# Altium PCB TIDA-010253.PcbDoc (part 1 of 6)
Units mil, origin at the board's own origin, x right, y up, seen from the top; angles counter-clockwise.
Board outline 5525 x 6695 mil, 4 copper layers (Top Layer, Signal Layer 1, Signal Layer 2, Bottom Layer), stack 61.2 mil thick; 522 components, 391 nets, 1722 pads, 1048 vias.
Unrouted connection lines stored in the file: 22.
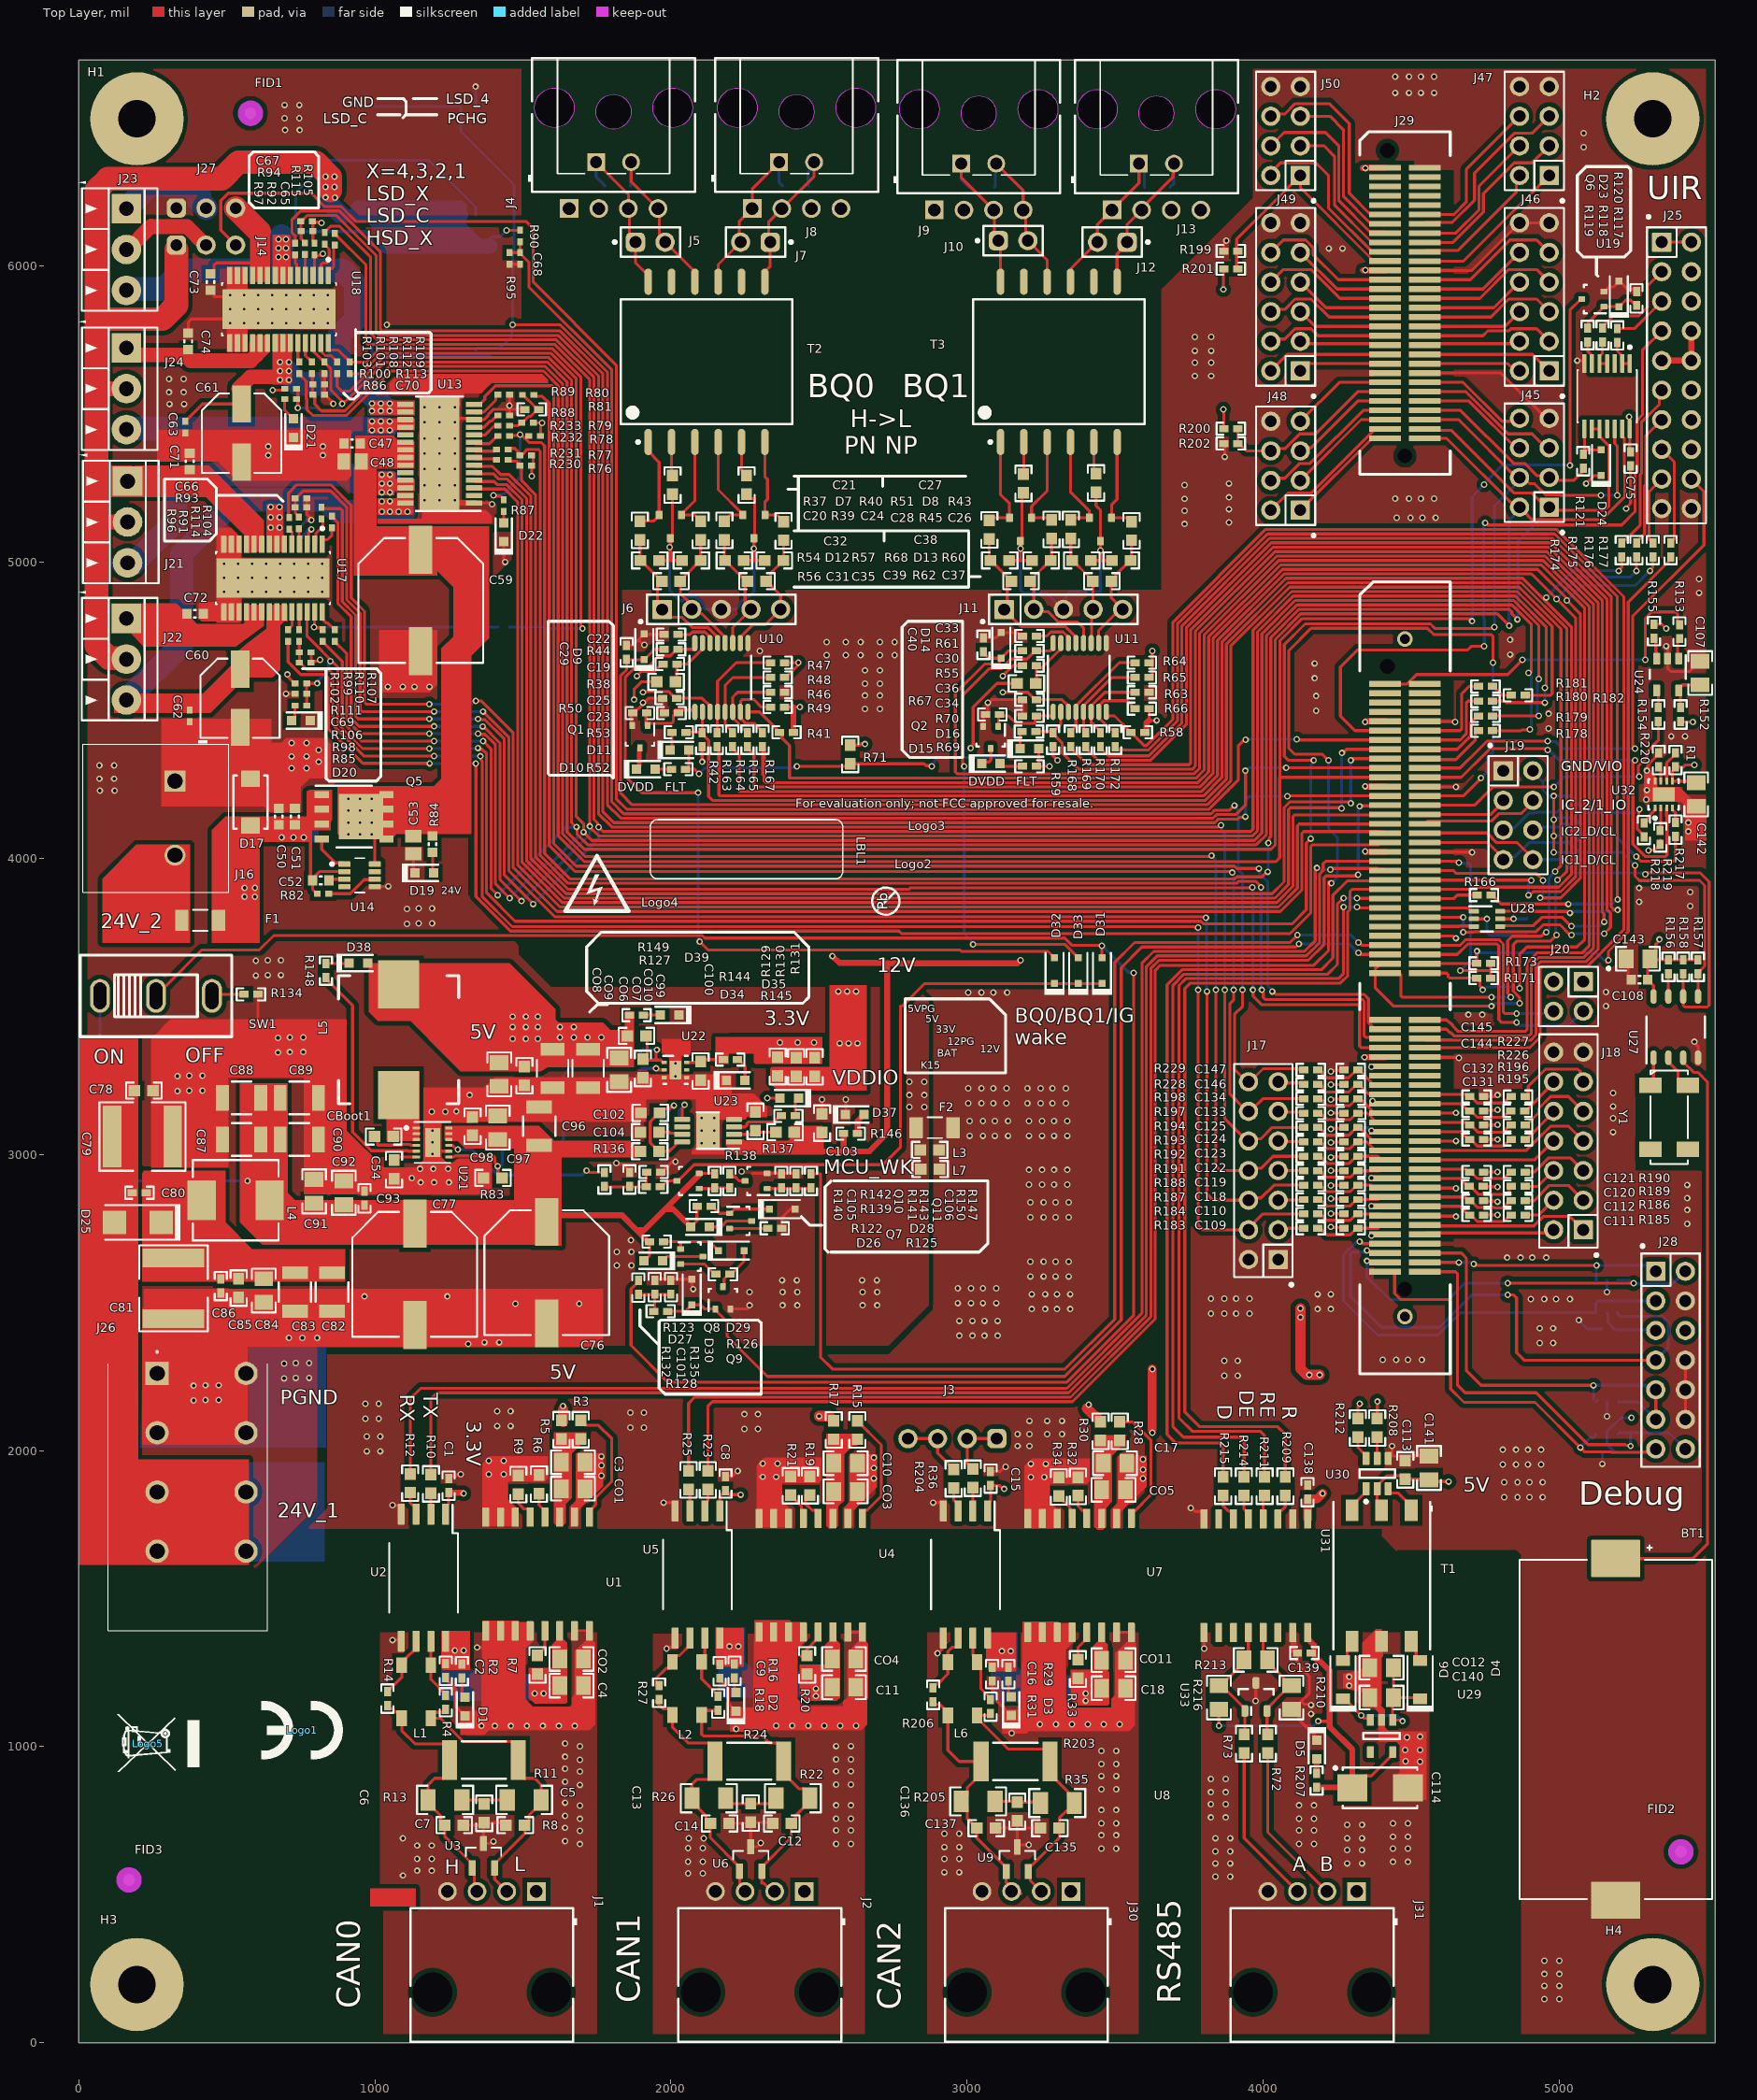
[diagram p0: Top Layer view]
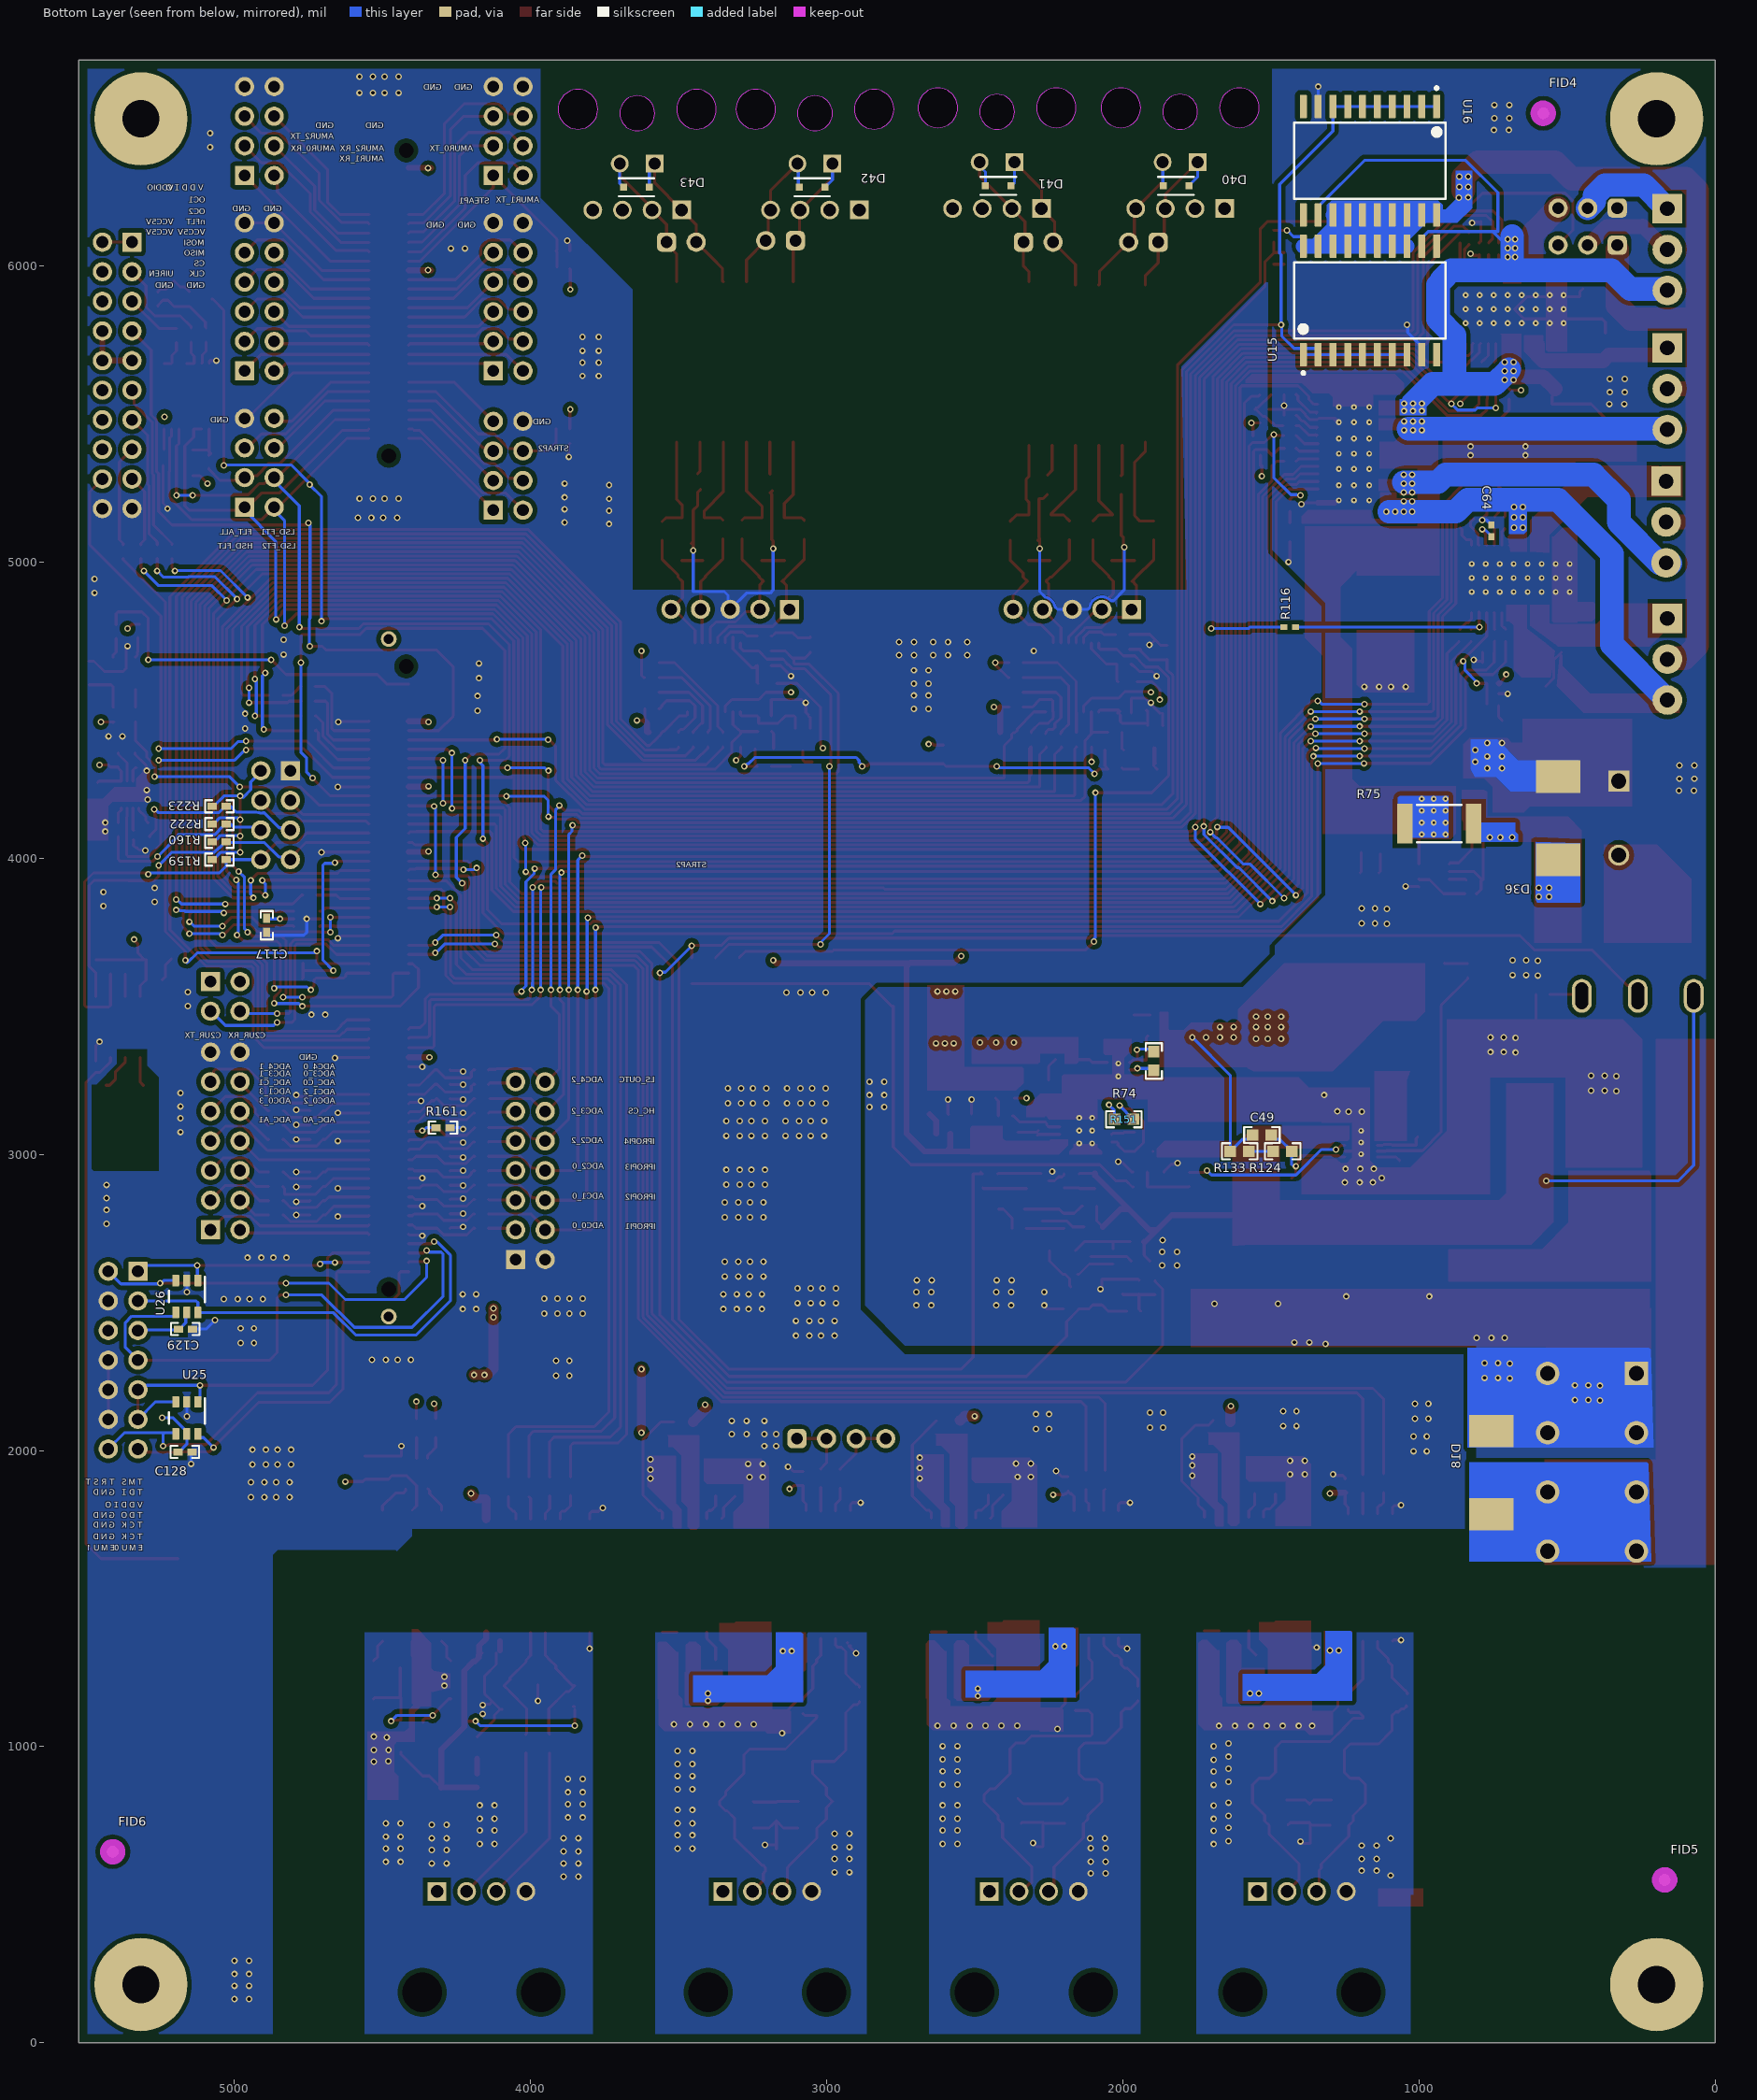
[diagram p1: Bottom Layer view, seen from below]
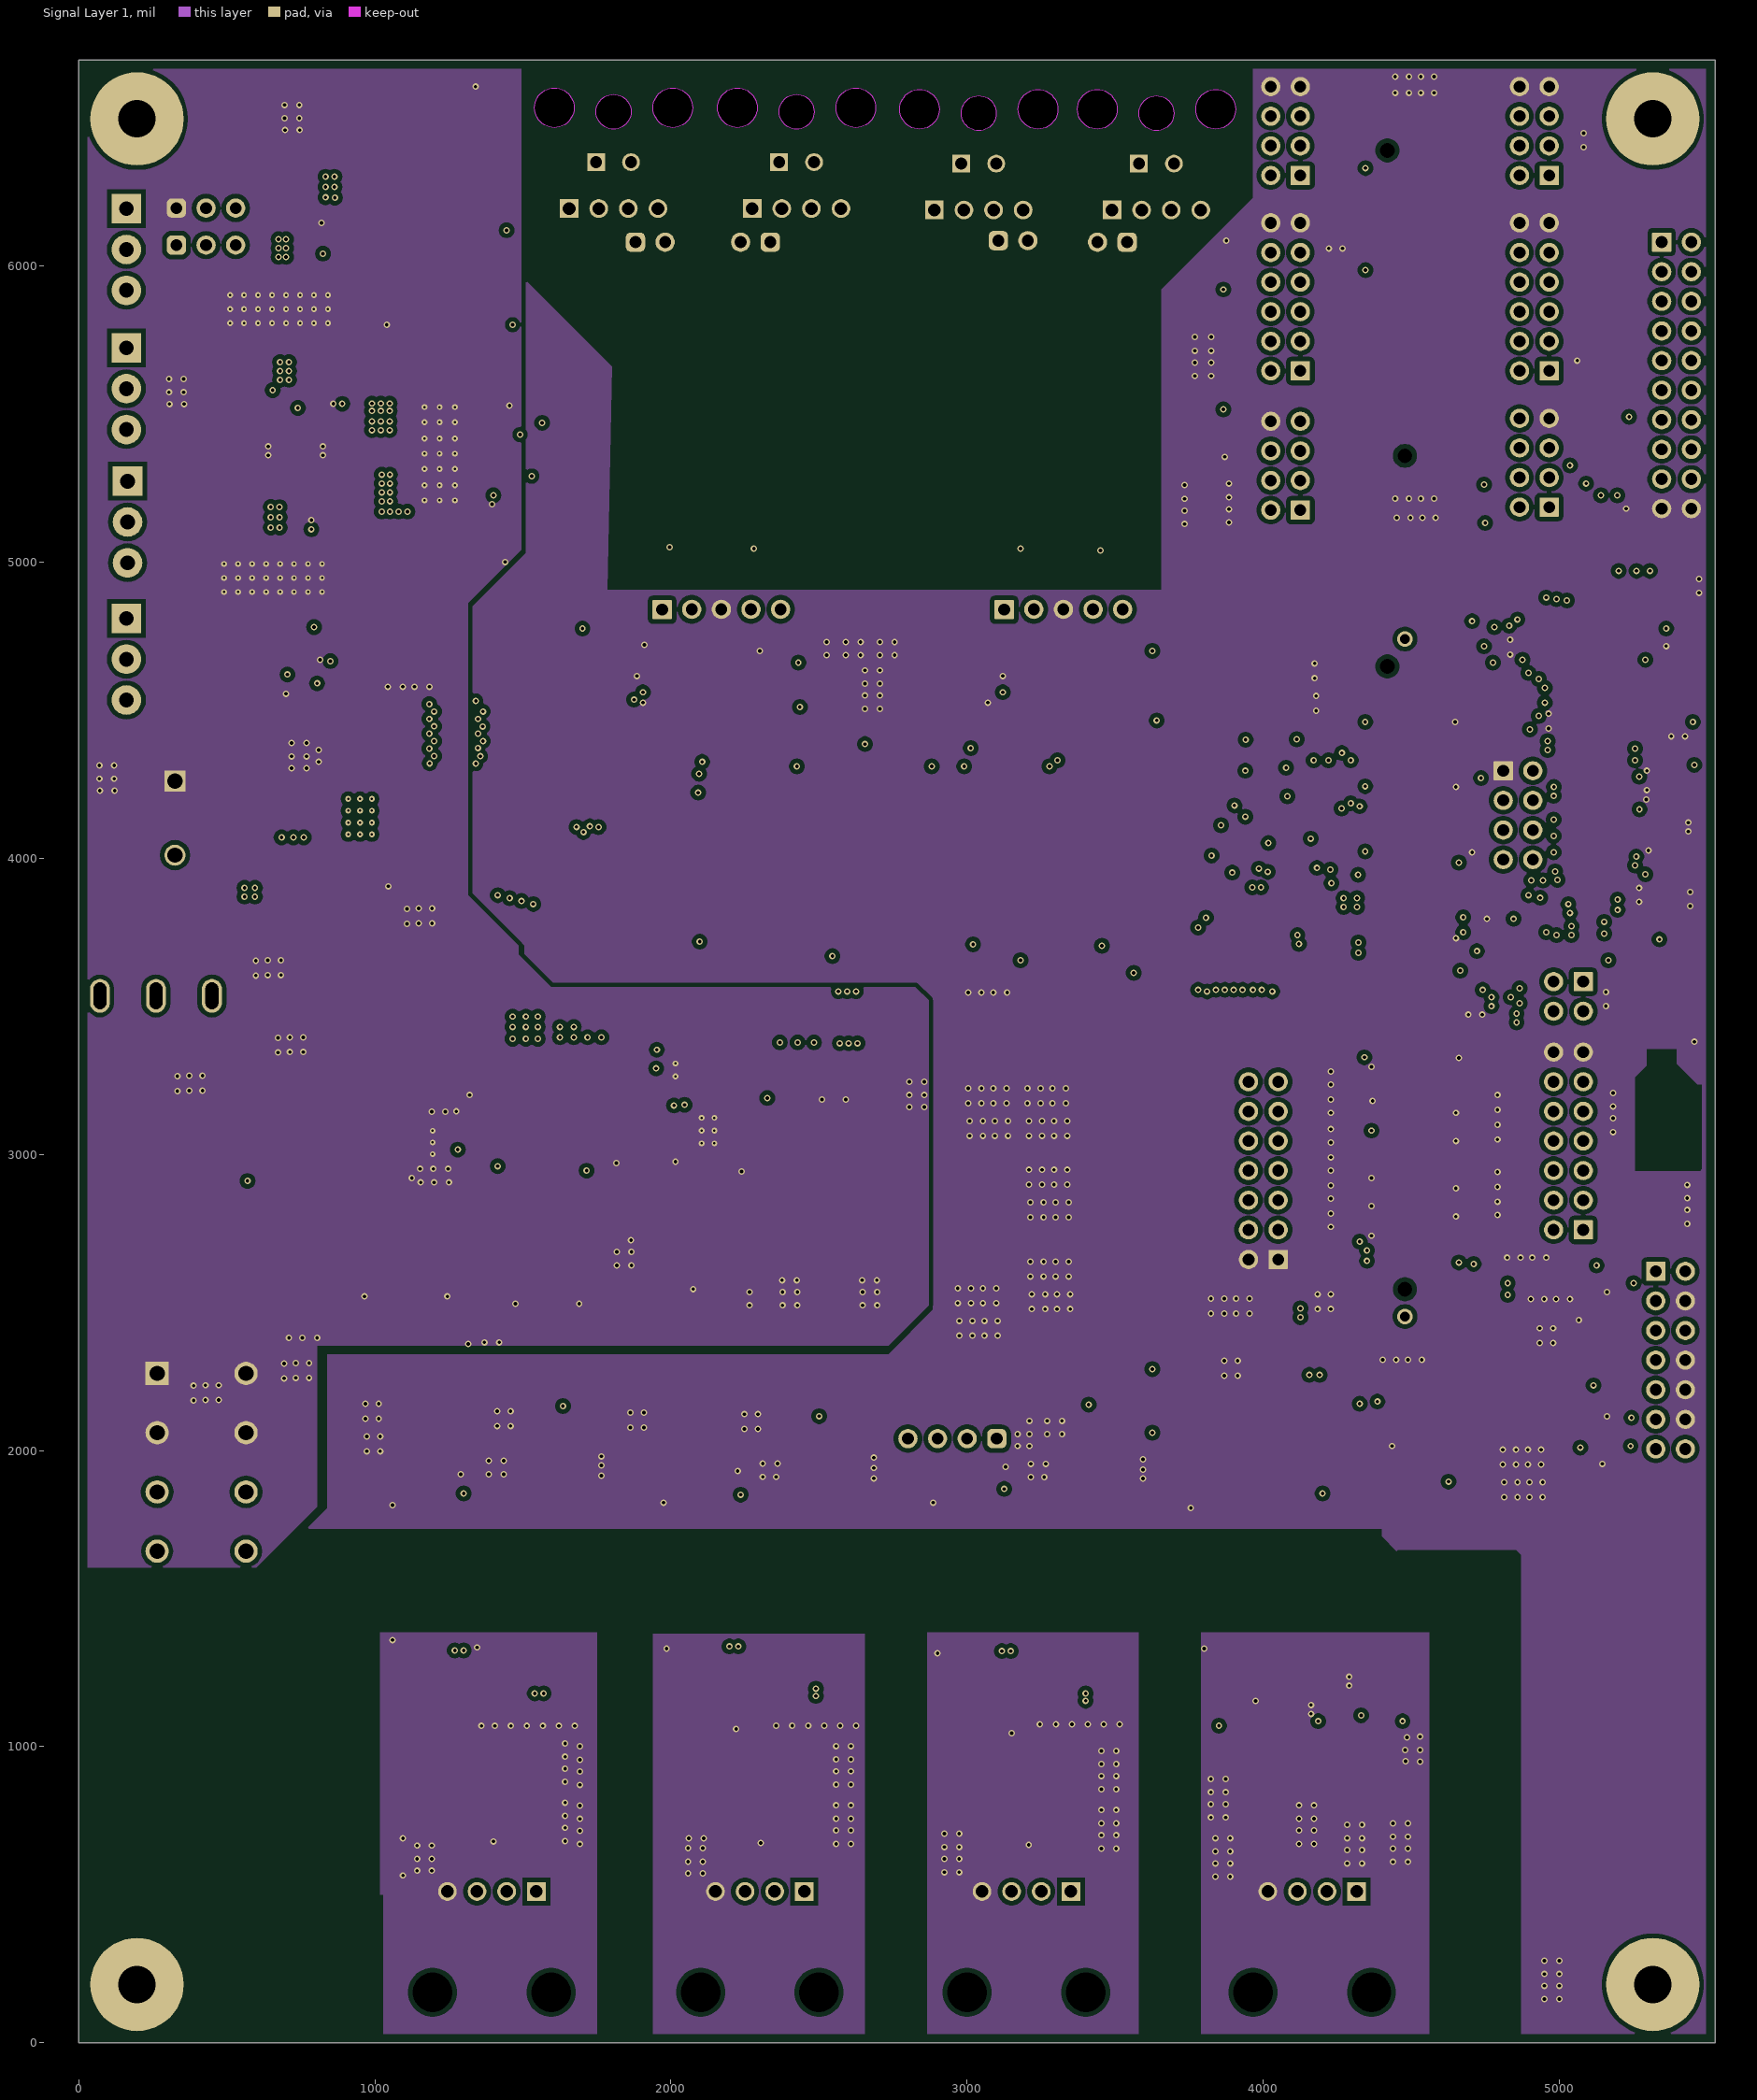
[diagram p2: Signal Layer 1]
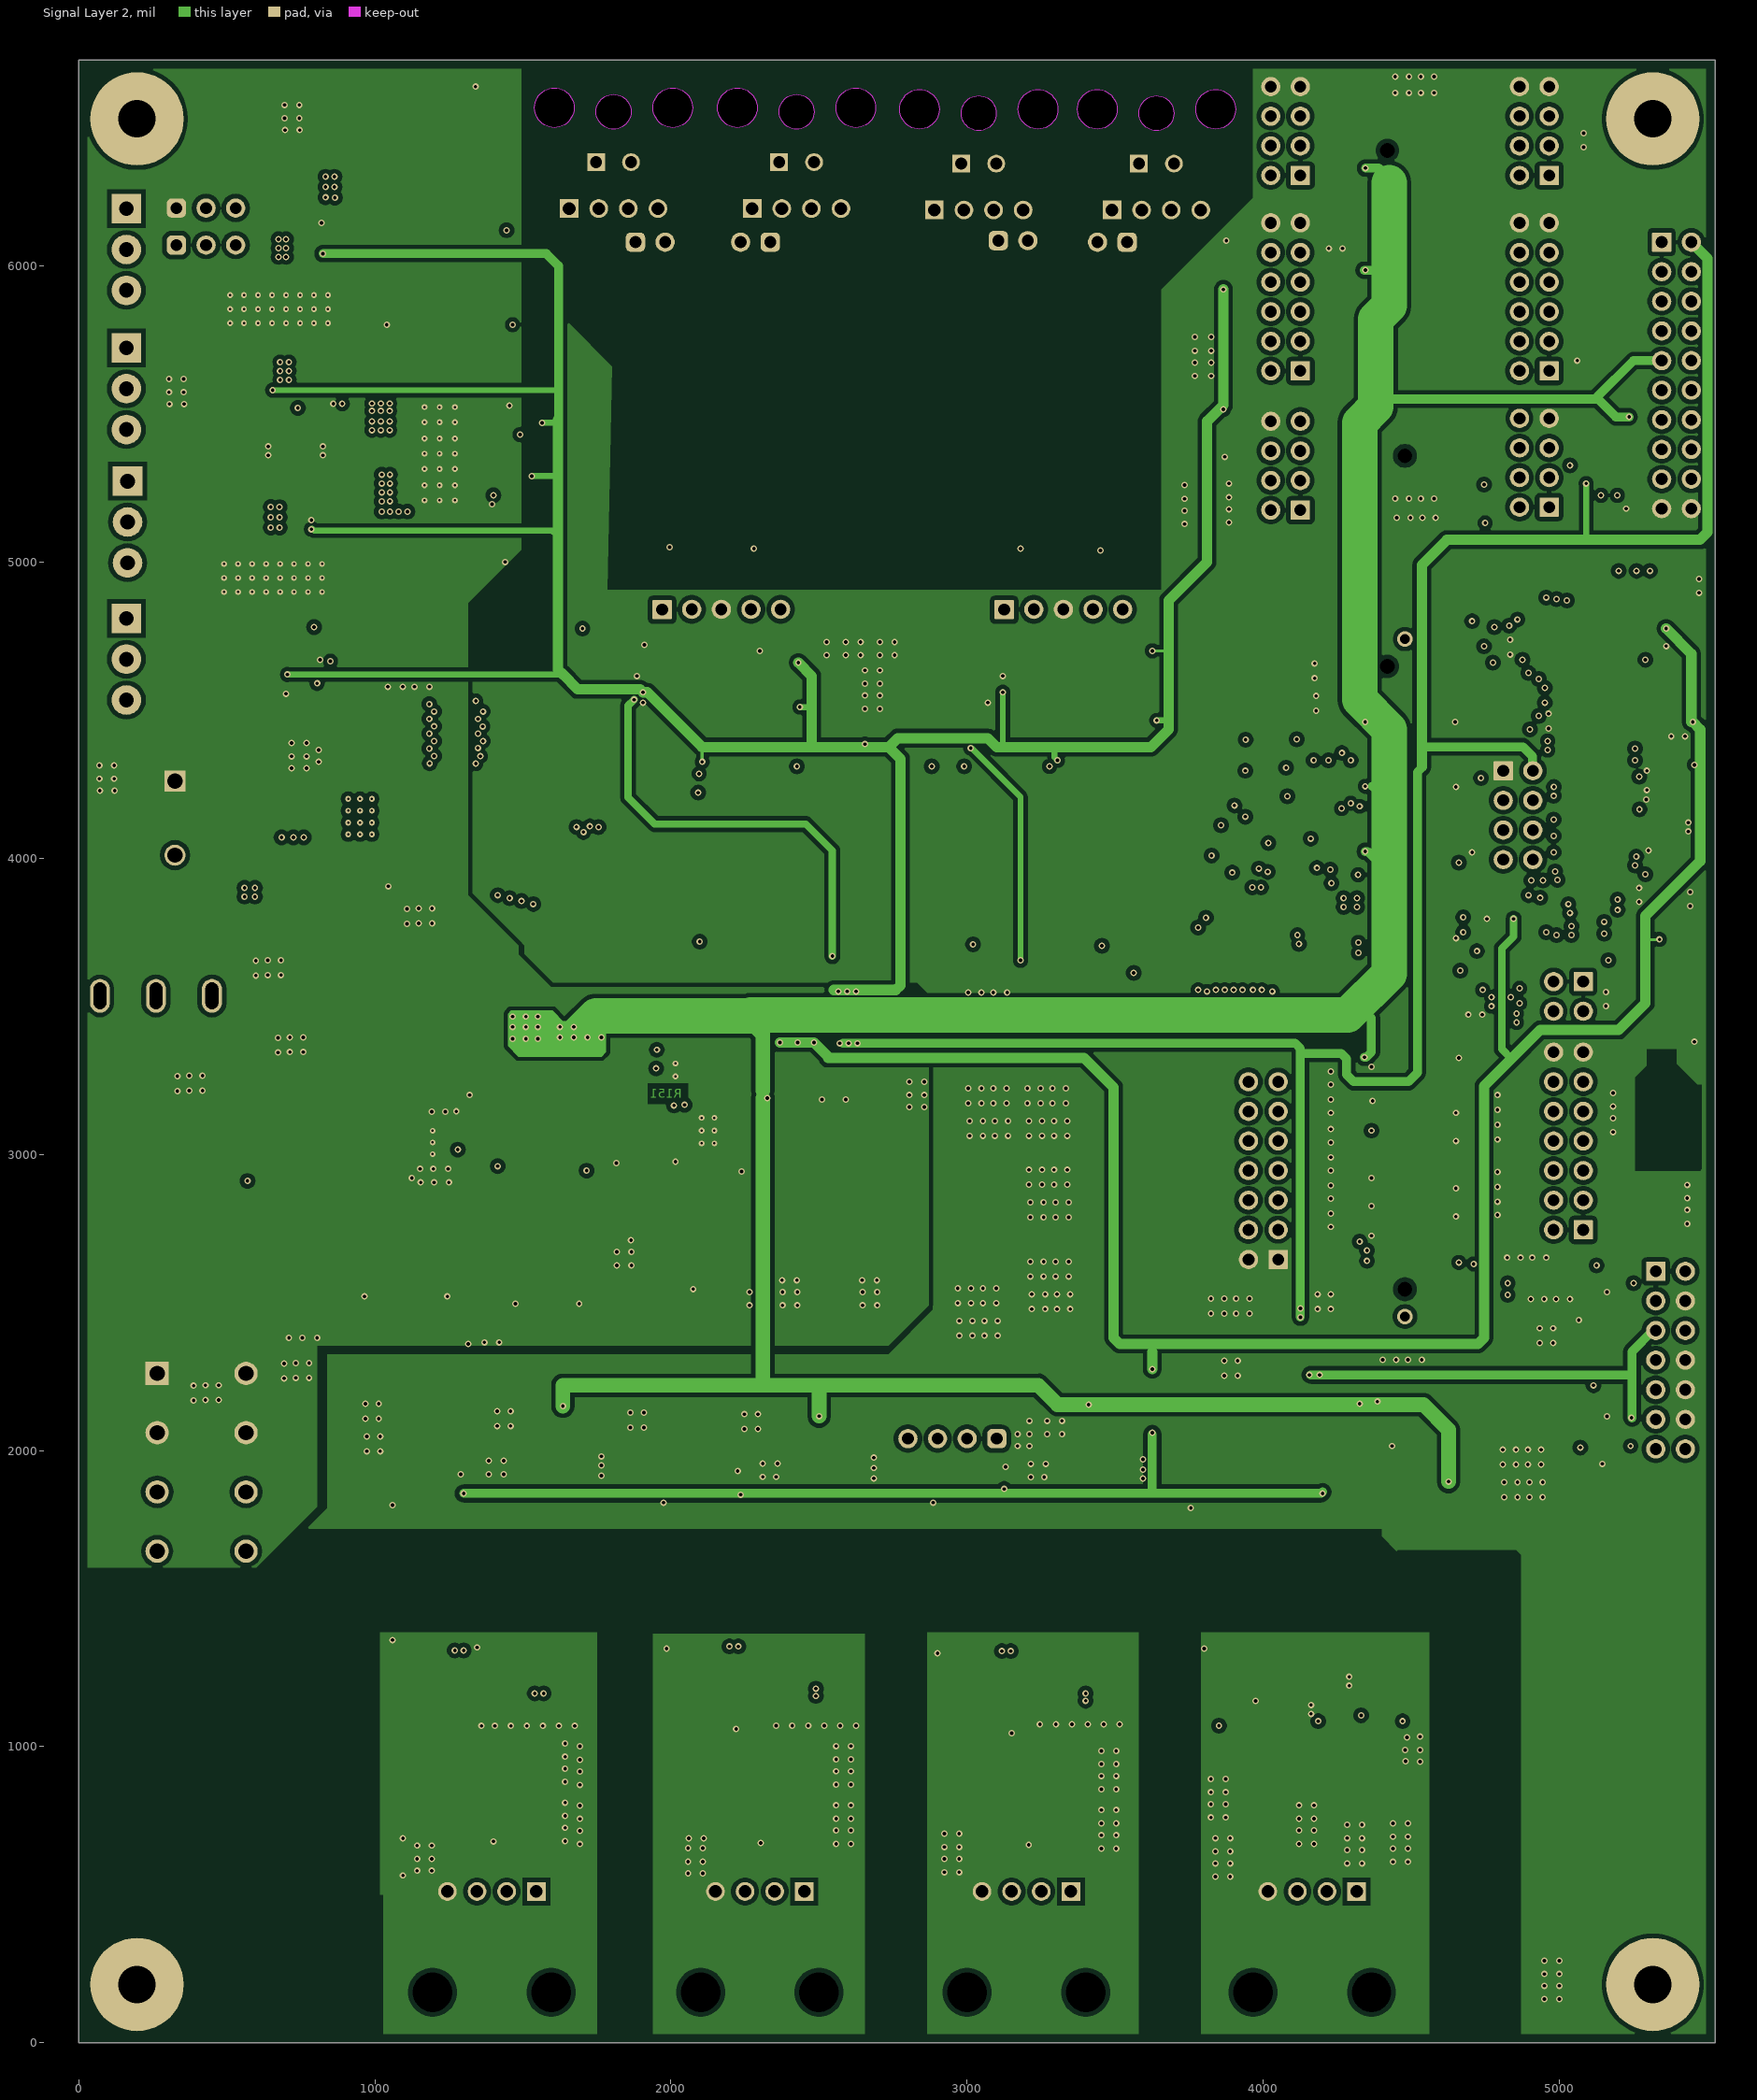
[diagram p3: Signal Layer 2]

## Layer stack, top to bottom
Top Solder: solder mask 0.4, Solder Resist, Dk 3.5
Top Layer: signal copper 1.4
Dielectric 1: prepreg 8, PP-006, Dk 4.2
Signal Layer 1: signal copper 1.4
Dielectric 2: dielectric 39.6, FR-4, Dk 4.2
Signal Layer 2: signal copper 1.4
Dielectric 3: prepreg 8, PP-006, Dk 4.2
Bottom Layer: signal copper 1.4
Bottom Solder: solder mask 0.4, Solder Resist, Dk 3.5

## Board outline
0,0 5525,0 5525,6695 0,6695

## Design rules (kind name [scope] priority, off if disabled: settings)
AcuteAngle [All] p1: minimum=4.50000000000000E+0001 checktracksonly=FALSE
AssemblyTestPointUsage [All] p1: valid=2
BoardOutlineClearance Copper [OnCopper and IsPoly] p1: gap=30 ignorepadtopadclearanceinfootprint=FALSE except(0: Arc-SplitContinuation Track-SplitContinuation SMDPad-SplitContinuation THPad-SplitContinuation Via-SplitContinuation Fill-SplitContinuation Poly-SplitContinuation Region-SplitContinuation Text-SplitContinuation)
BoardOutlineClearance [All] p2: gap=0 ignorepadtopadclearanceinfootprint=FALSE
Clearance Clearance_POLY1V2 [InNamedPolygon('VDD1V2_L03_P005')] p1: gap=5 ignorepadtopadclearanceinfootprint=FALSE except(0: Arc-Hole Track-Hole SMDPad-Hole THPad-Hole Via-Hole Fill-Hole Poly-Hole Region-Hole Text-Hole; 15: Fill-Fill Fill-Poly Fill-Region Poly-Poly Poly-Region Region-Region)
Clearance Clearance_Poly [InPolygon] p2: gap=15 ignorepadtopadclearanceinfootprint=FALSE except(0: Arc-Hole Track-Hole SMDPad-Hole THPad-Hole Via-Hole Fill-Hole Poly-Hole Region-Hole Text-Hole)
Clearance Clearance_Antenna [HasFootprint('0-MFG')] p3: gap=0 ignorepadtopadclearanceinfootprint=FALSE
Clearance Clearance_FiducialMark [HasFootprint('Fiducial10-20')] p4: gap=0 ignorepadtopadclearanceinfootprint=FALSE
Clearance [All] p5: gap=5 ignorepadtopadclearanceinfootprint=TRUE except(0: Arc-Hole Track-Hole SMDPad-Hole THPad-Hole Via-Hole Fill-Hole Poly-Hole Region-Hole Text-Hole)
ComponentClearance [All] p1: gap=0 collisioncheckmode=3 verticalgap=10 showdistances=FALSE
DiffPairsRouting [All] p1: maxlimit=100 minlimit=6 mostfreqgap=8 toplayer_minwidth=6 toplayer_maxwidth=10 toplayer_prefwidth=8.31 midlayer1_minwidth=6 midlayer1_maxwidth=10 midlayer1_prefwidth=8.31 midlayer2_minwidth=6 midlayer2_maxwidth=10 midlayer2_prefwidth=8.31 bottomlayer_minwidth=6 bottomlayer_maxwidth=10 bottomlayer_prefwidth=8.31 maxuncoupledlength=1000
FabricationTestPointUsage TestPointUsage [All] p1: valid=2 allowmultiple=FALSE
FabricationTestpoint Testpoint [All] p1: side=3 testpointundercomponent=TRUE minsize=40 maxsize=100 preferedsize=60 minholesize=0 maxholesize=40 preferedholesize=32 testpointgrid=1 allowsidetop=TRUE allowsidebottom=TRUE usegrid=TRUE gridtolerance=0.01
FanoutControl Fanout_LCC [IsLCC] p1: bgadir=Out bgaviamode=Centered fanoutstyle=Auto fanoutdirection=Alternating viagrid=1 // Fanout_LCC (Default Rule)
FanoutControl Fanout_BGA [IsBGA] p2: bgadir=Out bgaviamode=Centered fanoutstyle=Auto fanoutdirection=Alternating viagrid=1 // Fanout_BGA (Default Rule)
FanoutControl Fanout_Default [All] p4: bgadir=Out bgaviamode=Centered fanoutstyle=Auto fanoutdirection=Alternating viagrid=1 // Fanout_Default (Default Rule)
FanoutControl Fanout_Small [(CompPinCount < 5)] p5: bgadir=Out bgaviamode=Centered fanoutstyle=Auto fanoutdirection=OutThenIn viagrid=1 // Fanout_Small (Default Rule)
Height [All] p1: minheight=0 maxheight=10000 prefheight=500
HoleSize [All] p1: absolutevalues=TRUE maxlimit=251 minlimit=4 maxpercent=80.000 minpercent=20.000
HoleToHoleClearance [All] p1: gap=6 allowstackedmicrovias=TRUE
MinimumAnnularRing MinimumAnnularRing_ThermalPadVias [IsVia and InAnyComponent] p1: minimumring=5.91
MinimumAnnularRing [All] p2: minimumring=1.5
MinimumSolderMaskSliver MinimumSolderMaskSliver_Logo [InComponentClass('Logo') vs InComponentClass('Logo')] p1: minsoldermaskwidth=0.7
MinimumSolderMaskSliver [All] p2: minsoldermaskwidth=2
NetAntennae GNDGuard [InNet('GND')] p1: netantennaetolerance=200
NetAntennae [All] p2: netantennaetolerance=0
PlaneConnect [All] p1: planeconnectstyle=Relief reliefexpansion=10 reliefentries=4 reliefconductorwidth=10 reliefairgap=10
PolygonConnect [All] p1: connectstyle=Direct reliefconductorwidth=10 reliefentries=4 polygonreliefangle="90 Angle" airgapwidth=10
RoutingVias ThermalPadVias [IsVia and InAnyComponent] p1: holewidth=7.87 width=19.68 viastyle="Through Hole" minholewidth=5 minwidth=8 maxholewidth=12.99 maxwidth=23.62
RoutingVias [All] p2: holewidth=16 width=34 viastyle="Through Hole" minholewidth=4 minwidth=8 maxholewidth=40 maxwidth=65
ShortCircuit ShortCircuit_ANT [HasFootprint('0-MFG')] p1: allowed=TRUE
ShortCircuit [All] p2: allowed=FALSE
SilkToSilkClearance SilkToSilkClearance_Pb-FreeLogo [(HasFootprint('Pb-Free_Overlay_Medium') OR HasFootprint('Pb-Free_Overlay_Small')) vs (HasFootprint('Pb-Free_Overlay_Medium') OR HasFootprint('Pb-Free_Overlay_Small'))] p1: silktosilkclearance=0
SilkToSilkClearance [All] p2: silktosilkclearance=1
SilkToSolderMaskClearance IX61 [HasFootprint('IX61G-A-10P')] p1: minsilkscreentomaskgap=0 clearancetoexposedcopper=TRUE
SilkToSolderMaskClearance SilkToComponentPadClearance [(IsPad or IsFill or IsRegion) and InAnycomponent] p2: minsilkscreentomaskgap=3 clearancetoexposedcopper=TRUE
SilkToSolderMaskClearance "Silk to Solder Mask Opening" [All] p3: minsilkscreentomaskgap=3 clearancetoexposedcopper=FALSE
SolderMaskExpansion [All] p1: expansion=1.97 istentingtop=FALSE
Width [All] p1: maxlimit=120 minlimit=7 preferedwidth=10 checkconnectedcopper=TRUE
12 further rules are at their usual default settings.

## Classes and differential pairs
component class U_PowerSupply: C49 C54 C76 C77 C78 C79 C80 C81 C82 C83 C84 C85 C86 C87 C88 C89 C90 C91 C92 C93 C96 C97 C98 C99 C100 C101 C102 C103 C104 C105 C106 CBoot1 CO6 CO7 CO8 CO9 CO10 D18 D25 D26 D27 D28 D29 D30 D31 D32 D33 D34 D35 D37 D38 D39 F2 J26 L3 L4 L5 L7 Q7 Q8 Q9 Q10 Q11 R74 R83 R122 R123 R124 R125 R126 R127 R128 R129 R130 R131 R132 R133 R134 R135 R136 R137 R138 R139 R140 R141 R142 R143 R144 R145 R146 R147 R148 R149 R150 R151 SW1 U21 U22 U23
component class U_MCU_DockHearder_V3: BT1 C107 C108 C109 C110 C111 C112 C117 C118 C119 C120 C121 C122 C123 C124 C125 C128 C129 C131 C132 C133 C134 C142 C143 C144 C145 C146 C147 J17 J18 J19 J20 J28 J29 J45 J46 J47 J48 J49 J50 R1 R152 R153 R154 R155 R156 R157 R158 R159 R160 R161 R163 R164 R165 R166 R167 R168 R169 R170 R171 R172 R173 R174 R175 R176 R177 R178 R179 R180 R181 R182 R183 R184 R185 R186 R187 R188 R189 R190 R191 R192 R193 R194 R195 R196 R197 R198 R199 R200 R201 R202 R217 R218 R219 R220 R222 R223 R226 R227 R228 R229 U24 U25 U26 U27 U28 U32 Y1
component class "U_Driver and output": C47 C48 C50 C51 C52 C53 C59 C60 C61 C62 C63 C64 C65 C66 C67 C68 C69 C70 C71 C72 C73 C74 C75 D17 D19 D20 D21 D22 D23 D24 D36 F1 J14 J16 J21 J22 J23 J24 J25 J27 Q5 Q6 R75 R76 R77 R78 R79 R80 R81 R82 R84 R85 R86 R87 R88 R89 R90 R91 R92 R93 R94 R95 R96 R97 R98 R99 R100 R101 R102 R103 R104 R105 R106 R107 R108 R109 R110 R111 R112 R113 R114 R115 R116 R117 R118 R119 R120 R121 R230 R231 R232 R233 U13 U14 U15 U16 U17 U18 U19
component class U_DaisyChain: C19 C20 C21 C22 C23 C24 C25 C26 C27 C28 C29 C30 C31 C32 C33 C34 C35 C36 C37 C38 C39 C40 D7 D8 D9 D10 D11 D12 D13 D14 D15 D16 D40 D41 D42 D43 J4 J5 J6 J7 J8 J9 J10 J11 J12 J13 Q1 Q2 R37 R38 R39 R40 R41 R42 R43 R44 R45 R46 R47 R48 R49 R50 R51 R52 R53 R54 R55 R56 R57 R58 R59 R60 R61 R62 R63 R64 R65 R66 R67 R68 R69 R70 R71 T2 T3 U10 U11
component class "U_BCU Board_CAN485": C1 C2 C3 C4 C5 C6 C7 C8 C9 C10 C11 C12 C13 C14 C15 C16 C17 C18 C113 C114 C135 C136 C137 C138 C139 C140 C141 CO1 CO2 CO3 CO4 CO5 CO11 CO12 D1 D2 D3 D4 D5 D6 J1 J2 J3 J30 J31 L1 L2 L6 R2 R3 R4 R5 R6 R7 R8 R9 R10 R11 R12 R13 R14 R15 R16 R17 R18 R19 R20 R21 R22 R23 R24 R25 R26 R27 R28 R29 R30 R31 R32 R33 R34 R35 R36 R72 R73 R203 R204 R205 R206 R207 R208 R209 R210 R211 R212 R213 R214 R215 R216 T1 U1 U2 U3 U4 U5 U6 U7 U8 U9 U29 U30 U31 U33
component class U_BCU_HARDWARE: !PCB1 FID1 FID2 FID3 FID4 FID5 FID6 H1 H2 H3 H4 LBL1 Logo2 Logo4

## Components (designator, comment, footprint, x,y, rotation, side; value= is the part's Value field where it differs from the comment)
BT1 "BU2032SM-G" FP-BU2032SM-G_SMT2-MFG 5190,1058.23 r270 top
C1 "GCM155R71A104KA55D" 0402 1249.17,1881.02 r270 top value=0.1uF
C2 "GCM155R71A104KA55D" 0402 1239.17,1256.38 r90 top value=0.1uF
C3 "CL21B106KOQNNNE" 0805_HV 1669.17,1960 r0 top value=10uF
C4 "CL21B106KOQNNNE" 0805_HV 1664.17,1206.02 r0 top value=10uF
C5 "GRM1885C2A680JA01D" 0603 1474.17,735 r180 top value=68pF
C6 "GRM188R71H472KA01D" 0603 1369.17,775 r90 top value=4700pF
C7 "GRM1885C2A680JA01D" 0603 1267.67,735 r180 top value=68pF
C8 "GCM155R71A104KA55D" 0402 2184.17,1888.41 r270 top value=0.1uF
C9 "GCM155R71A104KA55D" 0402 2164.17,1254.49 r90 top value=0.1uF
C10 "CL21B106KOQNNNE" 0805_HV 2589.17,1956.89 r0 top value=10uF
C11 "CL21B106KOQNNNE" 0805_HV 2584.17,1200.87 r0 top value=10uF
C12 "GRM1885C2A680JA01D" 0603 2374.17,740.87 r180 top value=68pF
C13 "GRM188R71H472KA01D" 0603 2269.17,775.87 r90 top value=4700pF
C14 "GRM1885C2A680JA01D" 0603 2164.17,740.87 r180 top value=68pF
C15 "GCM155R71A104KA55D" 0402 3079.17,1905 r270 top value=0.1uF
C16 "GCM155R71A104KA55D" 0402 3084.17,1245 r90 top value=0.1uF
C17 "CL21B106KOQNNNE" 0805_HV 3499.17,1957.05 r0 top value=10uF
C18 "CL21B106KOQNNNE" 0805_HV 3494.17,1197.05 r0 top value=10uF
C19 "GCM155R71H104KE02D" 0402 1996.38,4655 r180 top value=0.1uF
C20 "CL10B221JB8NNNC" 0603 1928.5,5005 r0 top value=220pF
C21 "GCM1885C1H101JA16J" 0603 2005,5260 r90 top value=100pF
C22 "GCM155R71C224KE02D" 0402 2000,4755 r180 top value=0.22uF
C23 "GCM155R71C224KE02D" 0402 2001.38,4490 r180 top value=0.22uF
C24 "CL10B221JB8NNNC" 0603 2068.5,5005 r0 top value=220pF
C25 "GCM155R71H104KE02D" 0402 1995,4540 r180 top value=0.1uF
C26 "CL10B221JB8NNNC" 0603 2348.5,5005 r180 top value=220pF
C27 "GCM1885C1H101JA16J" 0603 2255,5260 r90 top value=100pF
C28 "CL10B221JB8NNNC" 0603 2213.5,5005 r180 top value=220pF
C29 "CGA2B3X7R1H103K050BB" 0402 1850,4695 r90 top value=0.01uF
C30 "GCM155R71H104KE02D" 0402 3210,4650 r180 top value=0.1uF
C31 "CL10B221JB8NNNC" 0603 3110,5004.93 r0 top value=220pF
C32 "GCM1885C1H101JA16J" 0603 3190.07,5265 r90 top value=100pF
C33 "GCM155R71C224KE02D" 0402 3210,4750 r180 top value=0.22uF
C34 "GCM155R71C224KE02D" 0402 3210,4480 r180 top value=0.22uF
C35 "CL10B221JB8NNNC" 0603 3250,5004.93 r0 top value=220pF
C36 "GCM155R71H104KE02D" 0402 3210,4535 r180 top value=0.1uF
C37 "CL10B221JB8NNNC" 0603 3520,5005 r180 top value=220pF
C38 "GCM1885C1H101JA16J" 0603 3435.07,5266.5 r90 top value=100pF
C39 "CL10B221JB8NNNC" 0603 3386.5,5005 r180 top value=220pF
C40 "CGA2B3X7R1H103K050BB" 0402 3055,4720 r90 top value=0.01uF
C47 "885012206095" 0603L 922.56,5400 r180 top value=0.1uF
C48 "C2012X6S1H225K125AB" 0805L 924.53,5340 r180 top value=2.2uF
C49 "06035A330JAT2A" 0603 1529.99,3065 r180 bottom value=33pF
C50 "C0603C101J5GAC" 0603L 675,4140 r90 top value=100pF
C51 "885012206095" 0603L 730,4140 r90 top value=0.1uF
C52 "CGA3E1X7R1E105K080AD" 0603L 817.44,3925 r0 top value=1uF
C53 "C2012X6S1H225K125AB" 0805L 1130,4044.53 r270 top value=2.2uF
C54 "CRCW060331K6FKEA" 0603 1064.99,2948.5 r90 top value=31.6k
C59 "EEE-FK1H151P" SM_RADIAL_G 1155,4870 r270 top value=150uF
C60 "EEE-FK1H100P" SM_RADIAL_D 545,4540 r270 top value=10uF
C61 "EEE-FK1H100P" SM_RADIAL_D 550,5435 r270 top value=10uF
C62 "C1005X7R1H104K050BE" 0402L 375,4480 r90 top value=0.1uF
C63 "C1005X7R1H104K050BE" 0402L 360,5455.31 r90 top value=0.1uF
C64 "C1005X7R1H104K050BE" 0402L 755,5104.69 r90 bottom value=0.1uF
C65 "C1005X7R1H104K050BE" 0402L 796.02,6057.01 r90 top value=0.1uF
C66 "GRM155R71H471KA01D" 0402L 750,5215 r0 top value=470pF
C67 "GRM155R71H471KA01D" 0402L 770,6150 r0 top value=470pF
C68 "GRM155R71H471KA01D" 0402L 1490,6024.69 r270 top value=470pF
C69 "GRM155R71H471KA01D" 0402L 765,4660 r0 top value=470pF
C70 "GRM155R71H471KA01D" 0402L 810,5565 r0 top value=470pF
C71 "C0603C102J5RACAUTO" 0603L 375,5340 r270 top value=1000pF
C72 "C0603C102J5RACAUTO" 0603L 392.44,4825 r180 top value=1000pF
C73 "C0603C102J5RACAUTO" 0603L 445,5945 r90 top value=1000pF
C74 "C0603C102J5RACAUTO" 0603L 370,5745 r270 top value=1000pF
C75 "GCM155R71H104KE02D" 0402 5240,5348.62 r270 top value=0.1uF
C76 "EEE-TP1V221AP" SM_RADIAL_G 1579.99,2600 r270 top value=220uF
C77 "EEE-TP1V221AP" SM_RADIAL_G 1135,2595 r270 top value=220uF
C78 "CGA3E2X7R2A472K080AA" 0603 220,3215 r0 top value=4700pF
C79 "CGA9P3X7S2A156M250KB" 2220_280 215,3060 r0 top value=15uF
C80 "GRM1555C1H102JA01D" 0402 205,2870 r180 top value=1000pF
C81 "CGA9P3X7S2A156M250KB" 2220_280 320,2547.64 r270 top value=15uF
C82 "CGA6P3X7S1H106K250AB" 1210_280 855,2535 r270 top value=10uF
C83 "CGA6P3X7S1H106K250AB" 1210_280 729.99,2535.04 r270 top value=10uF
C84 "CGA4J3X7R1H225K125AB" 0805_HV 624.99,2540 r270 top value=2.2uF
C85 "CGA3E3X8R1H104M080AB" 0603 539.99,2548.5 r270 top value=0.1uF
C86 "CGA2B2C0G1H102J050BA" 0402 479.99,2555 r270 top value=1000pF
C87 "CGA6P3X7S1H106K250AB" 1210_280 549.99,3050 r180 top value=10uF
C88 "CGA6P3X7S1H106K250AB" 1210_280 549.99,3191.08 r180 top value=10uF
C89 "CGA6P3X7S1H106K250AB" 1210_280 744.99,3191.08 r0 top value=10uF
C90 "CGA6P3X7S1H106K250AB" 1210_280 744.99,3050 r0 top value=10uF
C91 "CGA4J3X7R1H225K125AB" 0805_HV 795,2875 r90 top value=2.2uF
C92 "CGA4J3X7R1H225K125AB" 0805_HV 895,2870 r90 top value=2.2uF
C93 "CGA2B2C0G1H102J050BA" 0402 965,2851.38 r90 top value=1000pF
C96 "CGA6P3X7R1H475K250AB" 1210_280 1554.99,3095 r90 top value=4.7uF
C97 "08055C104JAT2A" 0805_HV 1414.99,3090 r90 top value=0.1uF
C98 "885012206083" 0603 1329.99,3095 r90 top value=1000pF
C99 "GCM188R71C105KA64D" 0603 1904.99,3290 r270 top value=1uF
C100 "GRT188R61C475KE13D" 0603 2099.99,3281.5 r270 top value=4.7uF
C101 "GCM155R71H104KE02D" 0402 1944.99,2551.38 r90 top value=0.1uF
C102 "GCM188R71C105KA64D" 0603 1929.99,3140 r180 top value=1uF
C103 "GRT188R61C475KE13D" 0603 2509.99,3105 r90 top value=4.7uF
C104 "885012206083" 0603 1928.49,3075 r180 top value=1000pF
C105 "GCM155R71H104KE02D" 0402 1859.99,2915 r90 top value=0.1uF
C106 "GCM155R71H104KE02D" 0402 2372.59,2910 r90 top value=0.1uF
C107 "08055C104JAT2A" 0805_HV 5475,4625 r90 top value=0.1uF
C108 "CGA3E1X7R1E105K080AD" 0603L 5269.94,3589.49 r180 top value=1uF
C109 "GCM155R71A104KA55D" 0402 4295,2750 r180 top value=0.1uF
C110 "GCM155R71A104KA55D" 0402 4295,2798.64 r180 top value=0.1uF
C111 "GCM155R71A104KA55D" 0402 4720,2795 r0 top value=0.1uF
C112 "GCM155R71A104KA55D" 0402 4720,2843.33 r0 top value=0.1uF
C113 "06033C104JAT2A" 0603 4479.17,1934.37 r90 top value=0.1uF
C114 "TPSC475K035R0600" 6032-28 4394.17,860.87 r0 top value=4.7uF
C117 "GCM155R71A104KA55D" 0402 4890,3773.62 r270 bottom value=0.1uF
C118 "GCM155R71A104KA55D" 0402 4295,2847.27 r180 top value=0.1uF
C119 "GCM155R71A104KA55D" 0402 4295,2895.91 r180 top value=0.1uF
C120 "GCM155R71A104KA55D" 0402 4718.62,2891.67 r0 top value=0.1uF
C121 "GCM155R71A104KA55D" 0402 4720,2940 r0 top value=0.1uF
C122 "GCM155R71A104KA55D" 0402 4295,2944.55 r180 top value=0.1uF
C123 "GCM155R71A104KA55D" 0402 4295,2993.18 r180 top value=0.1uF
C124 "GCM155R71A104KA55D" 0402 4295,3041.82 r180 top value=0.1uF
C125 "GCM155R71A104KA55D" 0402 4295,3090.45 r180 top value=0.1uF
C128 "GCM155R71A104KA55D" 0402 5166.38,1995 r180 bottom value=0.1uF
C129 "GCM155R71A104KA55D" 0402 5165,2410 r180 bottom value=0.1uF
C131 "GCM155R71A104KA55D" 0402 4720,3050 r0 top value=0.1uF
C132 "GCM155R71A104KA55D" 0402 4720,3098.33 r0 top value=0.1uF
C133 "GCM155R71A104KA55D" 0402 4296.38,3139.09 r180 top value=0.1uF
C134 "GCM155R71A104KA55D" 0402 4295,3187.73 r180 top value=0.1uF
C135 "GRM1885C2A680JA01D" 0603 3279.17,725 r180 top value=68pF
C136 "GRM188R71H472KA01D" 0603 3169.17,781.5 r90 top value=4700pF
C137 "GRM1885C2A680JA01D" 0603 3064.17,725 r180 top value=68pF
C138 "GCM155R71A104KA55D" 0402 4149.17,1859.25 r270 top value=0.1uF
C139 "GCM155R71A104KA55D" 0402 4138.62,1315.87 r0 top value=0.1uF
C140 "CL21B106KOQNNNE" 0805_HV 4399.17,1165.87 r180 top value=10uF
C141 "CL21B106KOQNNNE" 0805_HV 4559.17,1940.87 r90 top value=10uF
C142 "08055C104JAT2A" 0805_HV 5461.38,4215 r90 top value=0.1uF
C143 "08055C104JAT2A" 0805_HV 5265,3660 r180 top value=0.1uF
C144 "GCM155R71A104KA55D" 0402 4720,3146.67 r0 top value=0.1uF
C145 "GCM155R71A104KA55D" 0402 4720,3195 r0 top value=0.1uF
C146 "GCM155R71A104KA55D" 0402 4295,3236.36 r180 top value=0.1uF
C147 "GCM155R71A104KA55D" 0402 4295,3285 r180 top value=0.1uF
CBoot1 "06035C104KAT2A" 0603 1030,3060 r180 top value=0.1uF
CO1 "08055C104JAT2A" 0805_HV 1669.17,1871.02 r0 top value=0.1uF
CO2 "08055C104JAT2A" 0805_HV 1664.17,1296.02 r0 top value=0.1uF
CO3 "08055C104JAT2A" 0805_HV 2589.17,1861.89 r0 top value=0.1uF
CO4 "08055C104JAT2A" 0805_HV 2584.17,1295.87 r0 top value=0.1uF
CO5 "08055C104JAT2A" 0805_HV 3494.17,1867.05 r0 top value=0.1uF
CO6 "GRM32ER71A476ME15L" FP-GRM32ER71A476ME15L_1210-MFG 1599.99,3290 r90 top
CO7 "GRM32ER71A476ME15L" FP-GRM32ER71A476ME15L_1210-MFG 1719.99,3290 r90 top
CO8 "08055C104JAT2A" 0805_HV 1419.99,3270 r270 top value=0.1uF
CO9 "885012206083" 0603 1504.99,3265 r270 top value=1000pF
CO10 "08055C104JAT2A" 0805_HV 1824.99,3285 r270 top value=0.1uF
CO11 "08055C104JAT2A" 0805_HV 3494.17,1292.05 r0 top value=0.1uF
CO12 "08055C104JAT2A" 0805_HV 4399.17,1266.81 r180 top value=0.1uF
D1 "150060RS75000" WL-SMCW_RED 1304.17,1136.02 r90 top value=Red
D2 "150060RS75000" WL-SMCW_RED 2220,1150.87 r90 top value=Red
D3 "150060RS75000" WL-SMCW_RED 3149.17,1136.5 r90 top value=Red
D4 "1N5819HW-7-F" SOD-123 4529.17,1225.87 r90 top value=40V
D5 "150060RS75000" WL-SMCW_RED 4180,990.87 r270 top value=Red
D6 "1N5819HW-7-F" SOD-123 4269.17,1225.87 r90 top value=40V
D7 "PESD5V0L2BT,215" FP-PESD5V0L2BT,215_SOT23-3-MFG 1997.4,5119.43 r270 top
D8 "PESD5V0L2BT,215" FP-PESD5V0L2BT,215_SOT23-3-MFG 2280,5119.43 r270 top
D9 "SZMM3Z3V3ST1G" SOD-323 1910,4713.31 r90 top value=3.3V
D10 "150060VS75000" WL-SMCW_GREEN 1915,4300 r0 top value=Green
D11 "150060RS75000" WL-SMCW_RED 2028.5,4365 r0 top value=Red
D12 "PESD5V0L2BT,215" FP-PESD5V0L2BT,215_SOT23-3-MFG 3180,5110 r270 top
D13 "PESD5V0L2BT,215" FP-PESD5V0L2BT,215_SOT23-3-MFG 3450,5110 r270 top
D14 "SZMM3Z3V3ST1G" SOD-323 3115,4718.31 r90 top value=3.3V
D15 "150060VS75000" WL-SMCW_GREEN 3080,4320 r0 top value=Green
D16 "150060RS75000" WL-SMCW_RED 3210,4370 r0 top value=Red
D17 "SMAJ36CA" SMA_Bi 580,4189.33 r270 top value=36V
D18 "SMCJ33CA" SMC_Bi 755,1925 r270 bottom value=33V
D19 "150060VS75000" WL-SMCW_GREEN 1166.5,3950 r0 top value=Green
D20 "150060SS75000" WL-SMCW_RED 750,4465 r180 top value="Super Red"
D21 "150060SS75000" WL-SMCW_RED 725,5451.5 r90 top value="Super Red"
D22 "150060SS75000" WL-SMCW_RED 1435,5100 r90 top value="Super Red"
D23 "SZMM3Z3V3ST1G" SOD-323 5200,5905 r90 top value=3.3V
D24 "BAT54WSQ-7-F" SOD-323 5140,5335 r90 top value=30V
D25 "RB058L-60TE25" SMA 200,2770 r180 top value=60V
D26 "150060VS75000" WL-SMCW_GREEN 2098.49,2755 r180 top value=Green
D27 "150060VS75000" WL-SMCW_GREEN 1939.99,2640 r180 top value=Green
D28 "SZMM3Z3V3ST1G" SOD-323 2375,2815 r0 top value=3.3V
D29 "SZMM3Z3V3ST1G" SOD-323 2203.3,2675 r0 top value=3.3V
D30 "SZMM3Z3V3ST1G" SOD-323 2069.99,2535 r90 top value=3.3V
D31 "1N4148WS-7-F" SOD-323 3455,3620 r90 top value=75V
D32 "1N4148WS-7-F" SOD-323 3295,3620 r90 top value=75V
D33 "1N4148WS-7-F" SOD-323 3375,3620 r90 top value=75V
D34 "150060RS75000" WL-SMCW_RED 2218.49,3250 r0 top value=Red
D35 "150060RS75000" WL-SMCW_RED 2398.49,3190 r180 top value=Red
D36 "SMCJ36CA" SMC_Bi 530,4135 r270 bottom value=36V
D37 "150060RS75000" WL-SMCW_RED 2619.99,3135 r0 top value=Red
D38 "150060RS75000" WL-SMCW_RED 945,3645 r0 top value=Red
D39 "150060RS75000" WL-SMCW_RED 1994.99,3470 r180 top value=Red
D40 "CDSOD323-T08SC" SOD-323-Bi 1820,6270 r180 bottom value=8V
D41 "CDSOD323-T08SC" SOD-323-Bi 2420,6270 r0 bottom value=8V
D42 "CDSOD323-T08SC" SOD-323-Bi 3048.31,6265 r180 bottom value=8V
D43 "CDSOD323-T08SC" SOD-323-Bi 3641.69,6265 r0 bottom value=8V
F1 "BLM31KN121SZ1L" FP-BLM31KN121SZ1L_1206-MFG 410,3790 r0 top
F2 "BLM31KN121SZ1L" FP-BLM31KN121SZ1L_1206-MFG 2890,3090 r0 top
FID1 "Fiducial" Fiducial10-20 580,6515 r90 top
FID2 "Fiducial" Fiducial10-20 5410,645 r90 top
FID3 "Fiducial" Fiducial10-20 170,550 r90 top
FID4 "Fiducial" Fiducial10-20 580,6515 r90 bottom
FID5 "Fiducial" Fiducial10-20 170,550 r90 bottom
FID6 "Fiducial" Fiducial10-20 5410,645 r90 bottom
H1 "NY PMS 440 0025 PH" "NY PMS 440 0025 PH" 196.85,6496.06 r0 top
H2 "NY PMS 440 0025 PH" "NY PMS 440 0025 PH" 5314.96,6496.06 r0 top
H3 "NY PMS 440 0025 PH" "NY PMS 440 0025 PH" 196.85,196.85 r0 top
H4 "NY PMS 440 0025 PH" "NY PMS 440 0025 PH" 5314.96,196.85 r0 top
J1 "70551-0038" Molex_70551-0038 1395,511.02 r270 top
J2 "70551-0038" Molex_70551-0038 2300,511.02 r270 top
J3 "TSW-104-07-G-S" TSW-104-07-G-S 2950,2040 r180 top
J4 "DaisyChainConn_CoLay_34" DaisyChainConn_CoLay_34 1805.94,6193.31 r90 top
J5 "TSW-102-07-G-S" TSW-102-07-G-S 1930,6080 r0 top
J6 "TSW-105-07-G-S" TSW-105-07-X-S 2170,4840 r0 top
J7 "TSW-102-07-G-S" TSW-102-07-G-S 2285,6080 r180 top
J8 "DaisyChainConn_CoLay_12" DaisyChainConn_CoLay_12 2424.06,6193.31 r90 top
J9 "DaisyChainConn_CoLay_34" DaisyChainConn_CoLay_34 3039.06,6188.31 r90 top
J10 "TSW-102-07-G-S" TSW-102-07-G-S 3155,6085 r0 top
J11 "TSW-105-07-G-S" TSW-105-07-X-S 3325,4840 r0 top
J12 "TSW-102-07-G-S" TSW-102-07-G-S 3490,6080 r180 top
J13 "DaisyChainConn_CoLay_12" DaisyChainConn_CoLay_12 3639.06,6188.31 r90 top
J14 "TSW-103-07-G-S" TSW-103-07-G-S 430,6070 r0 top
J16 "1714955" Phoenix_1714955 325,4135 r270 top
J17 "TSW-107-07-G-D" TSW-107-07-X-D 4000,2945 r90 top
J18 "TSW-107-07-G-D" TSW-107-07-X-D 5030,3045 r90 top
J19 "TSW-104-07-G-D" TSW-104-07-G-D 4860,4145 r270 top
J20 "TSW-102-07-G-D" TSW-102-07-G-D 5030,3533 r180 top
J21 "ED555/3DS" TERM_BLK_ED555-3DS 165,5272.8 r270 top
J22 "ED555/3DS" TERM_BLK_ED555-3DS 161,4809.46 r270 top
J23 "ED555/3DS" TERM_BLK_ED555-3DS 161,6192.8 r270 top
J24 "ED555/3DS" TERM_BLK_ED555-3DS 161,5722.8 r270 top
J25 "TSW-110-07-G-D" TSW-110-07-G-D 5395,5630 r270 top
J26 "KF142R-5.08-4p" KF142R-5.08-4p 265,2260 r270 top
J27 "TSW-103-07-G-S" TSW-103-07-G-S 430,6195 r0 top
J28 "TSW-107-07-G-D" TSW-107-07-X-D 5375,2305 r270 top
J29 "HSEC8 180pin" HEADER_HSEC8_180_DV 4545,2603.74 r90 top
J30 "70551-0038" Molex_70551-0038 3200,511.02 r270 top
J31 "70551-0038" Molex_70551-0038 4165,511.02 r270 top
J45 "TSW-104-07-G-D" TSW-104-07-G-D 4915,5335 r90 top
J46 "TSW-106-07-G-D" TSW-106-07-G-D 4915,5895 r90 top
J47 "TSW-104-07-G-D" TSW-104-07-G-D 4915,6455 r90 top
J48 "TSW-104-07-G-D" TSW-104-07-G-D 4075,5325 r90 top
J49 "TSW-106-07-G-D" TSW-106-07-G-D 4075,5895 r90 top
J50 "TSW-104-07-G-D" TSW-104-07-G-D 4075,6455 r90 top
L1 "ACT45B-510-2P-TL003" ACT45B_NoSilk 1139.96,1185.43 r270 top value=51uH
L2 "ACT45B-510-2P-TL003" ACT45B_NoSilk 2054.17,1196.3 r270 top value=51uH
L3 "BLM18SG121TZ1D" 0603 2873.5,3015 r0 top
L4 "IHLP2525CZER2R2M5A" IHLP-2525CZ-5A 530,2845 r0 top value=2.2uH
L5 "74437368047" WE-LHMI_1040 1079.99,3387.01 r90 top value=4.7uH
L6 "ACT45B-510-2P-TL003" ACT45B_NoSilk 2984.17,1195.43 r270 top value=51uH
L7 "BLM18SG121TZ1D" 0603 2875,2950 r0 top
LBL1 "THT-14-423-10" Label_650x200 2255,4030 r0 top
Logo1 "CE Mark" CE_Mark_5mm 754.27,1055.3 r180 top
Logo2 "Pb-Free Symbol" Pb-Free_Overlay_Small 2725,3855 r90 top
Logo3 "FCC disclaimer" FCC_disclaimer 21025,4847 r90 top
Logo4 "DANGER HIGH VOLTAGE" IEC_HighVoltage_Small 1750,3910 r0 top
Logo5 "WEEE logo" WEEE_Minimum 234.27,1010.3 r90 top
Q1 "RJU003N03FRAT106" SOT-323 1895,4410 r270 top value=30V
Q2 "RJU003N03FRAT106" SOT-323 3079.41,4407.6 r270 top value=30V
Q5 "SIR662DP-T1-GE3" PowerPAK_SO-8 930,4140 r0 top value=60V
Q6 "RJU003N03FRAT106" SOT-323 5112.5,5887.5 r180 top value=30V
Q7 "BC847BW,115" SOT-323 2234.99,2775 r0 top value="45 V"
Q8 "BC847BW,115" SOT-323 2069.99,2655 r0 top value="45 V"
Q9 "RJU003N03FRAT106" SOT-323 2174.99,2515 r90 top value=30V
Q10 "BSS84AKW,115" SOT-323 2057.39,2910 r180 top value=-50V
Q11 "BC847BW,115" SOT-323 2287.59,2910 r180 top value="45 V"
R1 "RK73Z1ETTP" 0402 5391.38,4331.38 r270 top value=0
R2 "CRCW04023K30JNED" 0402 1294.17,1255 r270 top value=3.3k
R3 "CRCW06030000Z0EA" 0603 1695,2070 r90 top value=0
R4 "CRCW04020000Z0EDHP" 0402 1239.17,1150 r90 top value=0
R5 "CRCW06030000Z0EA" 0603 1630,2070 r270 top value=0
R6 "CRCW06030000Z0EA" 0603 1554.17,1886.02 r270 top value=0
R7 "CRCW06030000Z0EA" 0603 1549.17,1276.02 r270 top value=0
R8 "CRCW120659R0FKEA" 1206 1504.17,820 r0 top value=59.0
R9 "CRCW06030000Z0EA" 0603 1484.17,1884.53 r270 top value=0
R10 "CRCW06030000Z0EA" 0603 1189.17,1887.52 r270 top value=0
R11 "CRCW2512120RFKEG" 2512 1368.03,955 r0 top value=120
R12 "CRCW06030000Z0EA" 0603 1119.17,1889.53 r270 top value=0
R13 "CRCW120659R0FKEA" 1206 1237.08,820 r0 top value=59.0
R14 "CRCW04020000Z0EDHP" 0402 1042.57,1162.34 r90 top value=0
R15 "CRCW06030000Z0EA" 0603 2629.17,2069.37 r90 top value=0
R16 "CRCW04023K30JNED" 0402 2214.17,1255.87 r270 top value=3.3k
R17 "CRCW06030000Z0EA" 0603 2549.17,2069.37 r270 top value=0
R18 "CRCW04020000Z0EDHP" 0402 2159.17,1145.87 r90 top value=0
R19 "CRCW06030000Z0EA" 0603 2469.17,1880.87 r270 top value=0
R20 "CRCW06030000Z0EA" 0603 2459.17,1275.87 r270 top value=0
R21 "CRCW06030000Z0EA" 0603 2404.17,1880.87 r270 top value=0
R22 "CRCW120659R0FKEA" 1206 2411.25,825.87 r0 top value=59.0
R23 "CRCW06030000Z0EA" 0603 2124.17,1900.39 r270 top value=0
R24 "CRCW2512120RFKEG" 2512 2264.17,950.87 r0 top value=120
R25 "CRCW06030000Z0EA" 0603 2059.17,1900.39 r270 top value=0
R26 "CRCW120659R0FKEA" 1206 2127.91,825.87 r0 top value=59.0
R27 "CRCW04020000Z0EDHP" 0402 1960,1182.24 r90 top value=0
R28 "CRCW06030000Z0EA" 0603 3515,2065 r90 top value=0
R29 "CRCW04023K30JNED" 0402 3139.17,1245 r270 top value=3.3k
R30 "CRCW06030000Z0EA" 0603 3450,2065 r270 top value=0
R31 "CRCW04020000Z0EDHP" 0402 3079.17,1135 r90 top value=0
R32 "CRCW06030000Z0EA" 0603 3374.17,1878.54 r270 top value=0
R33 "CRCW06030000Z0EA" 0603 3374.17,1262.05 r270 top value=0
R34 "CRCW06030000Z0EA" 0603 3309.17,1877.05 r270 top value=0
R35 "CRCW120659R0FKEA" 1206 3304.17,809.59 r0 top value=59.0
R36 "CRCW06030000Z0EA" 0603 3019.17,1906.02 r270 top value=0
R37 "CRCW060351R0JNEA" 0603 1895,5106.5 r90 top value=51
R38 "CRCW060310R0JNEA" 0603 1983.5,4595 r180 top value=10
R39 "CRCW06031K00JNEA" 0603 2000,4935 r180 top value=1.0k
R40 "CRCW060351R0JNEA" 0603 2100,5106.5 r90 top value=51
R41 "CRCW040210K0JNED" 0402 2390,4425 r0 top value=10k
R42 "CRCW0402100KJNED" 0402 2105,4400 r270 top value=100k
R43 "CRCW060351R0JNEA" 0603 2380,5105 r90 top value=51
R44 "CRCW040239K0JNED" 0402 2000,4705 r0 top value=39k
R45 "CRCW06031K00JNEA" 0603 2290,4935 r0 top value=1.0k
R46 "CRCW040210K0JNED" 0402 2360,4560 r180 top value=10k
R47 "CRCW040210K0JNED" 0402 2360,4660 r180 top value=10k
R48 "CRCW040210K0JNED" 0402 2360,4610 r180 top value=10k
R49 "CRCW040210K0JNED" 0402 2360,4510 r180 top value=10k
R50 "CRCW040210M0FKED" 0402 1895,4490 r180 top value=10.0Meg
R51 "CRCW060351R0JNEA" 0603 2180,5106.5 r90 top value=51
R52 "CRCW04023K30JNED" 0402 2025,4300 r0 top value=3.3k
R53 "CRCW04023K30JNED" 0402 2026.38,4425 r180 top value=3.3k
R54 "CRCW060351R0JNEA" 0603 3075,5108.5 r90 top value=51
R55 "CRCW060310R0JNEA" 0603 3200,4590 r180 top value=10
R56 "CRCW06031K00JNEA" 0603 3181.5,4935.07 r180 top value=1.0k
R57 "CRCW060351R0JNEA" 0603 3285,5110 r90 top value=51
R58 "CRCW040210K0JNED" 0402 3576.38,4425 r0 top value=10k
R59 "CRCW0402100KJNED" 0402 3290,4400 r270 top value=100k
R60 "CRCW060351R0JNEA" 0603 3555,5105 r90 top value=51
R61 "CRCW040239K0JNED" 0402 3210,4700 r0 top value=39k
R62 "CRCW06031K00JNEA" 0603 3455,4935 r0 top value=1.0k
R63 "CRCW040210K0JNED" 0402 3590,4560 r180 top value=10k
R64 "CRCW040210K0JNED" 0402 3590,4660 r180 top value=10k
R65 "CRCW040210K0JNED" 0402 3590,4610 r180 top value=10k
R66 "CRCW040210K0JNED" 0402 3590,4505 r180 top value=10k
R67 "CRCW040210M0FKED" 0402 3085,4485 r180 top value=10.0Meg
R68 "CRCW060351R0JNEA" 0603 3350,5110 r90 top value=51
R69 "CRCW04023K30JNED" 0402 3210,4310 r0 top value=3.3k
R70 "CRCW04023K30JNED" 0402 3208.62,4427.31 r180 top value=3.3k
R71 "CRCW06030000Z0EA" 0603 2605,4350 r270 top value=0
R72 "CRCW06030000Z0EA" 0603 4015,1010 r270 top value=0
R73 "CRCW06030000Z0EA" 0603 3935,1010 r270 top value=0
R74 "CRCW06030000Z0EA" 0603 1894.99,3315 r90 bottom value=0
R75 "RMC1JPTE" 2512 931,4116.5 r0 bottom value=0
R76 "RC0402FR-0710KL" 0402L 1510,5325 r0 top value=10.0k
R77 "RC0402FR-0710KL" 0402L 1510,5360 r0 top value=10.0k
R78 "RC0402FR-0710KL" 0402L 1540,5425 r0 top value=10.0k
R79 "RC0402FR-0710KL" 0402L 1515.31,5470 r0 top value=10.0k
R80 "RC0402FR-0710KL" 0402L 1517.95,5563.98 r180 top value=10.0k
R81 "RC0402FR-07820RL" 0402 1530,5515 r0 top value=820
R82 "CRCW04020000Z0EDHP" 0402L 825.32,3880 r180 top value=0
R83 "RC0603FR-0716KL" 0603 1398.49,2920 r180 top value=16.0k
R84 "CRCW06034K99FKEAC" 0603L 1195,4047.56 r90 top value=4.99k
R85 "RC0402FR-071KL" 0402L 750,4515 r0 top value=1.00k
R86 "RC0402FR-071KL" 0402L 715,5550 r0 top value=1.00k
R87 "RC0402FR-071KL" 0402L 1435,5190 r90 top value=1.00k
R88 "CRCW04020000Z0EDHP" 0402L 1435,5495 r180 top value=0
R89 "CRCW04020000Z0EDHP" 0402L 1435,5565 r180 top value=0
R90 "RC0402FR-0715KL" 0402L 1490,6100 r90 top value=15.0k
R91 "CRCW04020000Z0EDHP" 0402L 743.52,5132.32 r90 top value=0
R92 "CRCW04020000Z0EDHP" 0402L 763.52,6057.32 r90 top value=0
R93 "RC0402FR-0710KL" 0402L 750,5185 r180 top value=10.0k
R94 "RC0402FR-0710KL" 0402L 770.71,6117.32 r180 top value=10.0k
R95 "RC0402FR-071KL" 0402L 1455,6025 r90 top value=1.00k
R96 "CRCW04020000Z0EDHP" 0402L 711.02,5130.35 r270 top value=0
R97 "CRCW04020000Z0EDHP" 0402L 731.02,6057.01 r270 top value=0
R98 "CRCW04025K60JNED" 0402L 750,4590 r180 top value=5.6k
R99 "CRCW04020000Z0EDHP" 0402L 744.41,4752.32 r270 top value=0
R100 "CRCW040212K0JNED" 0402L 715.32,5585 r180 top value=12k
R101 "CRCW04020000Z0EDHP" 0402L 787.5,5655 r270 top value=0
R102 "CRCW04020000Z0EDHP" 0402L 707.2,4752.32 r90 top value=0
R103 "CRCW04020000Z0EDHP" 0402L 745,5655 r90 top value=0
R104 "CRCW04020000Z0EDHP" 0402L 855,5135.31 r270 top value=0
R105 "CRCW04020000Z0EDHP" 0402L 865,6090 r270 top value=0
R106 "CRCW04028K25FKED" 0402L 750.31,4555 r0 top value=8.25k
R107 "CRCW04020000Z0EDHP" 0402L 865,4752.32 r90 top value=0
R108 "CRCW04028K25FKED" 0402L 830,5655.31 r90 top value=8.25k
R109 "CRCW04020000Z0EDHP" 0402L 915,5655 r90 top value=0
R110 "CRCW04020000Z0EDHP" 0402L 823.82,4752.32 r90 top value=0
R111 "RC0402FR-0710KL" 0402L 765,4695 r180 top value=10.0k
R112 "CRCW04020000Z0EDHP" 0402L 872.5,5655.31 r90 top value=0
R113 "RC0402FR-0710KL" 0402L 810,5600 r180 top value=10.0k
R114 "CRCW04020000Z0EDHP" 0402L 820,5165 r270 top value=0
R115 "CRCW04020000Z0EDHP" 0402L 831.02,6092.32 r270 top value=0
R116 "CRCW04020000Z0EDHP" 0402L 1435.31,4780 r0 bottom value=0
R117 "CRCW040233R0JNED" 0402 5195,5765 r270 top value=33
R118 "CRCW040233R0JNED" 0402 5145,5766.38 r270 top value=33
R119 "CRCW040233R0JNED" 0402 5095,5766.38 r270 top value=33
R120 "CRCW040210K0JNED" 0402 5260,5890 r270 top value=10k
R121 "CRCW0402100RJNED" 0402 5080,5340 r270 top value=100
R122 "CRCW0402100KJNED" 0402 2111.37,2825 r180 top value=100k
R123 "CRCW0402100KJNED" 0402 1951.37,2705 r180 top value=100k
R124 "RC0603FR-0734KL" 0603 1459.99,3010 r0 bottom value=34.0k
R125 "CRCW04023K30JNED" 0402 2349.99,2750 r180 top value=3.3k
R126 "CRCW04023K30JNED" 0402 2174.99,2595 r180 top value=3.3k
R127 "CRCW06030000Z0EA" 0603 1883.49,3400 r0 top value=0
R128 "CRCW040210K0JNED" 0402 1965,2470 r180 top value=10k
R129 "CRCW06030000Z0EA" 0603 2359.99,3296.5 r90 top value=0
R130 "CRCW06030000Z0EA" 0603 2422.49,3295 r90 top value=0
R131 "CRCW06030000Z0EA" 0603 2484.99,3295 r90 top value=0
R132 "CRCW04021K00JNED" 0402 1889.99,2550 r270 top value=1.0k
R133 "RC0603FR-0749K9L" 0603 1604.99,3010 r0 bottom value=49.9k
R134 "CRCW040210K0JNED" 0402 581.38,3540 r180 top value=10k
R135 "CRCW040210K0JNED" 0402 1999.99,2551.38 r270 top value=10k
R136 "CRCW06030000Z0EA" 0603 1928.49,3010 r0 top value=0
R137 "CRCW060310M0DHEAP" 0603 2384.99,3075 r0 top value=10Meg
R138 "CRCW06031M00DHEAP" 0603 2284.99,3111.5 r270 top value=1.00Meg
R139 "CRCW04021K00JNED" 0402 1939.99,2890 r180 top value=1.0k
R140 "CRCW04021K00JNED" 0402 1774.99,2915 r90 top value=1.0k
R141 "CRCW040210K0JNED" 0402 2147.39,2910 r90 top value=10k
R142 "CRCW040210K0JNED" 0402 1941.37,2940 r180 top value=10k
R143 "CRCW040210K0JNED" 0402 2197.59,2910 r270 top value=10k
R144 "CRCW04023K30JNED" 0402 2199.87,3320 r0 top value=3.3k
R145 "CRCW04026K80JNED" 0402 2396.37,3130 r180 top value=6.8k
R146 "CRCW040210K0JNED" 0402 2606.37,3070 r0 top value=10k
R147 "CRCW04023K30JNED" 0402 2472.59,2910 r270 top value=3.3k
R148 "CRCW04026K80JNED" 0402 835,3620 r270 top value=6.8k
R149 "CRCW04023K30JNED" 0402 1883.61,3470 r0 top value=3.3k
R150 "CRCW0402100KJNED" 0402 2422.59,2910 r270 top value=100k
R151 "CRCW06030000Z0EA" 0603 1995.82,3118.39 r0 bottom value=0
R152 "CRCW04020000Z0ED" 0402 5408.62,4485 r90 top value=0
R153 "CRCW04020000Z0ED" 0402 5405,4765 r90 top value=0
R154 "CRCW04020000Z0ED" 0402 5333.62,4485 r270 top value=0
R155 "CRCW04020000Z0ED" 0402 5318.62,4766.38 r270 top value=0
R156 "CRCW04024K70JNED" 0402 5367.5,3633.11 r90 top value=4.7k
R157 "CRCW04024K70JNED" 0402 5467.5,3633.11 r90 top value=4.7k
R158 "CRCW04024K70JNED" 0402 5417.5,3633.11 r90 top value=4.7k
R159 "CRCW04024K75FKED" 0402 5050,3995 r0 bottom value=4.75k
R160 "CRCW04024K75FKED" 0402 5050,4055 r0 bottom value=4.75k
R161 "RK73Z1ETTP" 0402 4295,3090 r0 bottom value=0
R163 "CRCW04020000Z0ED" 0402 2155,4400 r90 top value=0
R164 "CRCW04020000Z0ED" 0402 2207,4400 r90 top value=0
R165 "CRCW04020000Z0ED" 0402 2258,4400 r90 top value=0
R166 "CRCW04020000Z0ED" 0402 4745,3875 r0 top value=0
R167 "CRCW04020000Z0ED" 0402 2309,4400 r90 top value=0
R168 "CRCW04020000Z0ED" 0402 3350,4400 r90 top value=0
R169 "CRCW04020000Z0ED" 0402 3400,4400 r90 top value=0
R170 "CRCW04020000Z0ED" 0402 3450,4400 r90 top value=0
R171 "CRCW04020000Z0ED" 0402 4743.62,3595 r180 top value=0
R172 "CRCW04020000Z0ED" 0402 3500,4400 r90 top value=0
R173 "CRCW04020000Z0ED" 0402 4743.62,3645 r180 top value=0
R174 "CRCW04020000Z0ED" 0402 5210,5040 r90 top value=0
R175 "CRCW04020000Z0ED" 0402 5260,5040 r90 top value=0
R176 "CRCW04020000Z0ED" 0402 5315,5040 r90 top value=0
R177 "CRCW04020000Z0ED" 0402 5375,5040 r90 top value=0
R178 "CRCW04020000Z0ED" 0402 4750,4430 r0 top value=0
R179 "CRCW04020000Z0ED" 0402 4750,4480 r0 top value=0
R180 "CRCW04020000Z0ED" 0402 4750,4530 r0 top value=0
R181 "CRCW04020000Z0ED" 0402 4750,4580 r0 top value=0
R182 "CRCW04020000Z0ED" 0402 4860,4550 r0 top value=0
R183 "CRCW0402220RJNED" 0402 4160,2750 r180 top value=220
R184 "CRCW0402220RJNED" 0402 4160,2798.64 r180 top value=220
R185 "CRCW0402220RJNED" 0402 4860,2795 r0 top value=220
R186 "CRCW0402220RJNED" 0402 4860,2843.33 r0 top value=220
R187 "CRCW0402220RJNED" 0402 4160,2847.27 r180 top value=220
R188 "CRCW0402220RJNED" 0402 4160,2895.91 r180 top value=220
R189 "CRCW0402220RJNED" 0402 4860,2891.67 r0 top value=220
R190 "CRCW0402220RJNED" 0402 4860,2940 r0 top value=220
R191 "CRCW0402220RJNED" 0402 4160,2944.55 r180 top value=220
R192 "CRCW0402220RJNED" 0402 4160,2993.18 r180 top value=220
R193 "CRCW0402220RJNED" 0402 4160,3041.82 r180 top value=220
R194 "CRCW0402220RJNED" 0402 4160,3090.45 r180 top value=220
R195 "CRCW0402220RJNED" 0402 4860,3050 r0 top value=220
R196 "CRCW0402220RJNED" 0402 4860,3098.33 r0 top value=220
R197 "CRCW0402220RJNED" 0402 4160,3139.09 r180 top value=220
R198 "CRCW0402220RJNED" 0402 4160,3187.73 r180 top value=220
R199 "RC0402FR-0710KL" 0402 3890,5990 r180 top value=10.0k
R200 "RC0402FR-0710KL" 0402 3890,5450 r180 top value=10.0k
R201 "RC0402FR-0710KL" 0402 3890,6050 r180 top value=10.0k
R202 "RC0402FR-0710KL" 0402 3890,5400 r180 top value=10.0k
R203 "CRCW2512120RFKEG" 2512 3163.03,950 r0 top value=120
R204 "CRCW06030000Z0EA" 0603 2954.17,1904.53 r270 top value=0
R205 "CRCW120659R0FKEA" 1206 3037.08,815 r0 top value=59.0
R206 "CRCW04020000Z0EDHP" 0402 2885,1175 r90 top value=0
R207 "CRCW04023K30JNED" 0402 4180,885.87 r90 top value=3.3k
R208 "CRCW06030000Z0EA" 0603 4384.17,2075.87 r270 top value=0
R209 "CRCW06030000Z0EA" 0603 4074.17,1879.37 r270 top value=0
R210 "RR1220P-911-D" 0805_HV 4095,1165.87 r90 top value=910
R211 "CRCW06030000Z0EA" 0603 4004.17,1879.37 r270 top value=0
R212 "CRCW06030000Z0EA" 0603 4319.17,2075.87 r270 top value=0
R213 "ESR10EZPF1200" 0805_HV 3974.17,1292.87 r0 top value=120
R214 "CRCW06030000Z0EA" 0603 3934.17,1879.37 r270 top value=0
R215 "CRCW06030000Z0EA" 0603 3864.17,1879.37 r270 top value=0
R216 "RR1220P-911-D" 0805_HV 3850,1165.87 r90 top value=910
R217 "RK73Z1ETTP" 0402 5391.38,4096.38 r270 top value=0
R218 "RK73Z1ETTP" 0402 5285,4095 r270 top value=0
R219 "RK73Z1ETTP" 0402 5340,4070 r270 top value=0
R220 "RK73Z1ETTP" 0402 5335,4331.38 r90 top value=0
R222 "CRCW04024K75FKED" 0402 5050,4115 r0 bottom value=4.75k
R223 "CRCW04024K75FKED" 0402 5050,4175 r0 bottom value=4.75k
R226 "CRCW0402220RJNED" 0402 4858.62,3146.67 r0 top value=220
R227 "CRCW0402220RJNED" 0402 4860,3195 r0 top value=220
R228 "CRCW0402220RJNED" 0402 4160,3236.36 r180 top value=220
R229 "CRCW0402220RJNED" 0402 4160,3285 r180 top value=220
R230 "CRCW04020000Z0EDHP" 0402L 1430,5345 r0 top value=0
R231 "CRCW04020000Z0EDHP" 0402L 1430,5380 r0 top value=0
R232 "CRCW04020000Z0EDHP" 0402L 1435,5425 r0 top value=0
R233 "CRCW04020000Z0EDHP" 0402L 1435,5460 r0 top value=0
SW1 "SS12D10" SS12D10 260.91,3535 r0 top
T1 "750315371" Wurth_750315371 4399.17,1576.89 r270 top value=105uH
T2 "HMU2129NL" HMU2129NL 2120,5675.67 r90 top
T3 "HMU2129NL" HMU2129NL 3309.37,5675.67 r90 top
U1 "UCC12050DVE" DVE0016A 1549.17,1582.95 r270 top
U2 "ISO1042DWVR" DWV0008A 1164.17,1570.59 r270 top
U3 "ESD762DBZR" DBZ0003A-MFG 1366.77,631.34 r90 top
U4 "UCC12050DVE" DVE0016A 2471.67,1578.82 r270 top
U5 "ISO1042DWVR" DWV0008A 2089.17,1581.46 r270 top
U6 "ESD762DBZR" DBZ0003A-MFG 2269.17,620.87 r90 top
U7 "UCC12050DVE" DVE0016A 3379.17,1578.07 r270 top
U8 "ISO1042DWVR" DWV0008A 2994.17,1581.46 r270 top
U9 "ESD762DBZR" DBZ0003A-MFG 3169.17,620 r90 top
U10 "BQ79600PWQ1" PW0016A_N 2170,4610 r90 top
U11 "BQ79600PWQ1" PW0016A_N 3380,4610 r90 top
U13 "TPS4H160AQPWPRQ1" PWP0028C_N 1218.86,5365.43 r180 top
U14 "LM74701QDDFQ1" DDF0008A-MFG 948.82,3941.61 r0 top
U15 "ULN2803CDWR" FP-DW0020A-MFG 1165,5883.07 r90 bottom
U16 "ULN2803CDWR" FP-DW0020A-MFG 1165,6355 r270 bottom
U17 "DRV3946-Q1" PWP0028R-MFG 656.25,4945.83 r270 top
U18 "DRV3946-Q1" PWP0028R-MFG 676.42,5853.61 r270 top
U19 "SN74HCS21PWR" PW0014A-MFG 5160.59,5559.76 r270 top
U21 "LMR51450SDRRR" DRR0012E-MFG 1194.99,3040 r0 top
U22 "TPS7B8133QDRVRQ1" DRV0006A 2014.99,3285 r0 top
U23 "TPS7A1601DGNR" DGN0008C_N 2124.99,3080 r180 top
U24 "TPS3823-33DBVR" DBV0005A_N 5365,4620 r270 top
U25 "TPD4E001QDBVRQ1" DBV0006A_N 5160,2110 r270 bottom
U26 "TPD4E001QDBVRQ1" DBV0006A_N 5160,2520 r270 bottom
U27 "BQ32000DR" D0008A_L 5392.5,3429.49 r90 top
U28 "SN74LVC2G17QDCKRQ1" DCK0006A_N 4755,3795 r0 top
U29 "TPS76338DBVT" DBV0005A_N 4399.17,1035.87 r270 top
U30 "SN6505BQDBVTQ1" DBV0006A-MFG 4384.17,1922.05 r90 top
U31 "ISO1410DWR" DW0016B_HV 3974.17,1576.89 r270 top
U32 "HDC3020DEF" DEF0008A-MFG 5351.85,4214.72 r90 top
U33 "SM712.TCT" SOT-23 3975,1167.76 r90 top value="7V, 12V"
Y1 "MC-306 32.7680K-A0:ROHS" XTAL_MC-306 5370,3125 r0 top

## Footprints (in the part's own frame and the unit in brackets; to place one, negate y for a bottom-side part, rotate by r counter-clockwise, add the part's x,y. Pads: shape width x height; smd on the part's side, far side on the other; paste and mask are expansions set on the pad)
0402 [mm] "0402 from SM-752 data"
  rect 0.8x0.6 smd: 1(-0.6,0) 2(0.6,0)
  silkscreen extent -1.22,-0.52 1.22,0.52, body extent -0.55,-0.3 0.55,0.3, height 0.6
0402L [mm] "0402 from SM-752 data"
  rect 0.6x0.5 smd: 1(-0.5,0) 2(0.5,0)
  body extent -0.55,-0.3 0.55,0.3, height 0.6
0603 [mm] "0603 from SM-752 data"
  rect 1x0.95 smd: 1(-0.8,0) 2(0.8,0)
  silkscreen extent -1.52,-0.69 1.52,0.69, body extent -0.87,-0.47 0.87,0.47, height 1
0603L [mm] "0603 from SM-752 data"
  rect 0.8x0.85 smd: 1(-0.7,0) 2(0.7,0)
  silkscreen extent -0.07,-0.33 0.07,0.33, body extent -0.87,-0.47 0.87,0.47, height 1
0805_HV [mil] "0805 with 30mil clearance between pads"
  rect 50x63 smd: 1(-40,0) 2(40,0)
  silkscreen extent -74,-40 74,40, body extent -43,-29 43,29, height 57
0805L [mm] "0805 from SM-752 data"
  rect 1.1x1.4 smd: 1(-0.75,0) 2(0.75,0)
  body extent -1.1,-0.72 1.1,0.72, height 1.45
1206 [mm] "1206 from SM-752 data"
  rect 1.3x1.85 smd: 1(-1.45,0) 2(1.45,0)
  silkscreen extent -2.4,-1.21 2.4,1.21, body extent -1.7,-0.9 1.7,0.9, height 1.35
1210_280 [mm] "SMD, 2-Leads, Body 3.6x2.8mm, Height 2.8mm"
  rect 1.1x2.2 smd: 1(-1.65,0) 2(1.65,0)
  silkscreen extent -0.84,-1.4 0.84,1.4, body extent -1.8,-1.4 1.8,1.4, height 2.8
2220_280 [mm] "Chip Capacitor, Body 5.7x5.0mm, IPC Medium Density"
  rect 1.6x5.3 smd: 1(-2.6,0) 2(2.6,0)
  silkscreen extent -3.69,-2.94 3.69,2.94, body extent -2.95,-2.62 2.95,2.62, height 2.8
2512 [mm] "Chip Resistor, Body 6.3x3.2mm, IPC Medium Density"
  rect 1.3x3.4 smd: 1(-2.95,0) 2(2.95,0)
  silkscreen extent -1.9,-1.6 1.9,1.6, body extent -3.22,-1.67 3.22,1.67, height 0.71
6032-28 [mm] "Medium Density IPC based on Vishay Sprague 293D datasheet."
  rect 2.55x2.3 smd: 1(-2.375,0) 2(2.375,0)
  silkscreen extent -3.96,-1.75 3.2,1.82, body extent -3.15,-1.75 3.15,1.75, height 2.8
ACT45B_NoSilk [mm] "SMD, 4-Leads, Body 4.7 x 3.7 mm"
  rect 1.35x0.9 smd: 1(-2.275,1.25) 2(-2.275,-1.25) 3(2.275,-1.25) 4(2.275,1.25)
  body extent -2.35,-1.7 2.35,1.7, height 3
CE_Mark_5mm [mil] "Minimum text height for CE Mark"
  silkscreen extent -138,-98 138,98
D0008A_L [mm] "SOIC, 8-Leads, Body 4.9x3.9mm, Pitch 1.27mm, IPC High Density"
  oval 1.25x0.55 smd: 1(-2.625,1.905) 2(-2.625,0.635) 3(-2.625,-0.635) 4(-2.625,-1.905) 5(2.625,-1.905) 6(2.625,-0.635) 7(2.625,0.635) 8(2.625,1.905)
  silkscreen extent -3.1,-2.5 0.9,2.5, body extent -3,-2.45 3,2.45, height 1.63
DaisyChainConn_CoLay_12 [mm] "Header(shrouded), 2.54mm, 4x1, R/A, TH"
  rect 1.6x1.6 hole 1.09: 1(0,3.81)
  rect 1.52x1.52 hole 1.02 mask+0.076: 1(3.98,1.5)
  round 1.6 hole 1.09: 2(0,1.27) 3(0,-1.27) 4(0,-3.81)
  round 1.52 hole 1.02 mask+0.076: 2(3.98,-1.5)
  Keep-Out Layer board cut-out: 8.3,1.5 8.874,1.386 9.361,1.061 9.686,0.574 9.8,0 9.8,0 9.686,-0.574 9.361,-1.061 8.874,-1.386 8.3,-1.5 8.3,-1.5 7.726,-1.386 7.239,-1.061 6.914,-0.574 6.8,0 6.8,0 6.914,0.574 7.239,1.061 7.726,1.386 8.3,1.5
  Keep-Out Layer board cut-out: 8.64,-3.38 9.291,-3.509 9.842,-3.878 10.211,-4.429 10.34,-5.08 10.34,-5.08 10.211,-5.731 9.842,-6.282 9.291,-6.651 8.64,-6.78 8.64,-6.78 7.989,-6.651 7.438,-6.282 7.069,-5.731 6.94,-5.08 6.94,-5.08 7.069,-4.429 7.438,-3.878 7.989,-3.509 8.64,-3.38
  Keep-Out Layer board cut-out: 8.64,6.78 9.291,6.651 9.842,6.282 10.211,5.731 10.34,5.08 10.34,5.08 10.211,4.429 9.842,3.878 9.291,3.509 8.64,3.38 8.64,3.38 7.989,3.509 7.438,3.878 7.069,4.429 6.94,5.08 6.94,5.08 7.069,5.731 7.438,6.282 7.989,6.651 8.64,6.78
  silkscreen extent 1.45,-6.98 12.9,7.32, body extent -0.71,-6.98 12.88,6.98, height 6.6
DaisyChainConn_CoLay_34 [mm] "Header(shrouded), 2.54mm, 4x1, R/A, TH"
  rect 1.6x1.6 hole 1.09: 1(0,3.81)
  round 1.6 hole 1.09: 2(0,1.27) 3(0,-1.27) 4(0,-3.81)
  rect 1.52x1.52 hole 1.02 mask+0.076: 3(3.98,1.5)
  round 1.52 hole 1.02 mask+0.076: 4(3.98,-1.5)
  Keep-Out Layer board cut-out: 8.64,6.78 9.291,6.651 9.842,6.282 10.211,5.731 10.34,5.08 10.34,5.08 10.211,4.429 9.842,3.878 9.291,3.509 8.64,3.38 8.64,3.38 7.989,3.509 7.438,3.878 7.069,4.429 6.94,5.08 6.94,5.08 7.069,5.731 7.438,6.282 7.989,6.651 8.64,6.78
  Keep-Out Layer board cut-out: 8.64,-3.38 9.291,-3.509 9.842,-3.878 10.211,-4.429 10.34,-5.08 10.34,-5.08 10.211,-5.731 9.842,-6.282 9.291,-6.651 8.64,-6.78 8.64,-6.78 7.989,-6.651 7.438,-6.282 7.069,-5.731 6.94,-5.08 6.94,-5.08 7.069,-4.429 7.438,-3.878 7.989,-3.509 8.64,-3.38
  Keep-Out Layer board cut-out: 8.3,1.5 8.874,1.386 9.361,1.061 9.686,0.574 9.8,0 9.8,0 9.686,-0.574 9.361,-1.061 8.874,-1.386 8.3,-1.5 8.3,-1.5 7.726,-1.386 7.239,-1.061 6.914,-0.574 6.8,0 6.8,0 6.914,0.574 7.239,1.061 7.726,1.386 8.3,1.5
  silkscreen extent 1.45,-6.98 12.9,7.32, body extent -0.71,-6.98 12.88,6.98, height 6.6
DBV0005A_N [mm] "SOT23, 5-Leads, Body 2.9x1.6mm, Pitch 0.95mm, Lead Span 2.8mm, IPC Medium Density"
  rrect17% 1x0.6 smd: 1(-1.375,0.95) 2(-1.375,0) 3(-1.375,-0.95) 4(1.375,-0.95) 5(1.375,0.95)
  silkscreen extent -1.63,-1.55 0.38,1.55, body extent -1.42,-1.46 1.42,1.46, height 1.09
DBV0006A-MFG [mm]
  rrect17% 1.1x0.6 smd paste+0 mask+0: 1(-1.3,0.95) 2(-1.3,0) 3(-1.3,-0.95) 4(1.3,-0.95) 5(1.3,0) 6(1.3,0.95)
  silkscreen extent -2.52,-1.53 0.35,1.53, body extent -1.95,-1.78 1.95,1.78, height 0.25
DBV0006A_N [mm] "SOT23, 6-Leads, Body 2.9x1.6mm, Pitch 0.95mm, Lead Span 2.8mm, IPC Medium Density"
  rrect17% 1x0.6 smd: 1(-1.375,0.95) 2(-1.375,0) 3(-1.375,-0.95) 4(1.375,-0.95) 5(1.375,0) 6(1.375,0.95)
  silkscreen extent -1.68,-1.55 0.5,1.55, body extent -1.42,-1.46 1.42,1.46, height 1.12
DBZ0003A-MFG [mm]
  rrect17% 1.3x0.6 smd paste+0 mask+0: 1(-1.05,0.95) 2(-1.05,-0.95) 3(1.05,0)
  silkscreen extent -0.03,-1.52 0.7,1.52, body extent -1.8,-1.62 1.8,1.62, height 0.25
DCK0006A_N [mm] "SOT23, 6-Leads, Body 2x1.3mm, Pitch 0.65mm, Lead Span 2.1mm, IPC Medium Density"
  rrect25% 0.85x0.4 smd: 1(-1.125,0.65) 2(-1.125,0) 3(-1.125,-0.65) 4(1.125,-0.65) 5(1.125,0) 6(1.125,0.65)
  silkscreen extent -1.5,-1.09 0.51,1.09, body extent -1.14,-1 1.14,1, height 0.95
DDF0008A-MFG [mm]
  rrect22% 1.05x0.45 smd paste+0 mask+0: 1(-1.3,0.975) 2(-1.3,0.325) 3(-1.3,-0.325) 4(-1.3,-0.975) 5(1.3,-0.975) 6(1.3,-0.325) 7(1.3,0.325) 8(1.3,0.975)
  silkscreen extent -2.5,-1.48 0.4,1.48, body extent -1.92,-1.73 1.92,1.73, height 0.25
DEF0008A-MFG [mm]
  rrect40% 0.6x0.25 smd paste+0 mask+0: 1(-1.15,0.75) 2(-1.15,0.25) 3(-1.15,-0.25) 4(-1.15,-0.75) 5(1.15,-0.75) 6(1.15,-0.25) 7(1.15,0.25) 8(1.15,0.75)
  rrect8% 1.2x1.9 smd paste-1000 mask+0: 9(0,0)
  silkscreen extent -2.15,-1.3 1.3,1.3, body extent -1.55,-1.4 1.55,1.4, height 0.25
DGN0008C_N [mm] "TSOP, 8-Leads, Body 3x3mm, Pitch 0.65mm, Thermal Pad 1.98x1.88mm, IPC Medium Density"
  rrect22% 1.35x0.45 smd: 1(-2.225,0.975) 2(-2.225,0.325) 3(-2.225,-0.325) 4(-2.225,-0.975) 5(2.225,-0.975) 6(2.225,-0.325) 7(2.225,0.325) 8(2.225,0.975)
  rrect10% 2x3 smd paste-2 mask-2: 9(0,0)
  rrect6% 1.6x1.92 on Top Solder: 9(0,0)
  rrect6% 1.6x1.92 on Top Paste: 9(0,0)
  silkscreen extent -2.65,-1.55 0.95,1.55, body extent -2.45,-1.5 2.45,1.5, height 1.1
DRR0012E-MFG [mm]
  rrect40% 0.62x0.25 smd paste+0 mask+0: 1(-1.39,1.25) 2(-1.39,0.75) 3(-1.39,0.25) 4(-1.39,-0.25) 5(-1.39,-0.75) 6(-1.39,-1.25) 7(1.39,-1.25) 8(1.39,-0.75) 9(1.39,-0.25) 10(1.39,0.25) 11(1.39,0.75) 12(1.39,1.25)
  rrect8% 1.3x2.5 smd paste-1000 mask+0: 13(0,0)
  silkscreen extent -2.37,-1.75 1.55,1.75, body extent -1.8,-1.65 1.8,1.65, height 0.25
DRV0006A [mm] "SON, 6-Leads, Body 2x2mm, Pitch 0.65mm, Thermal Pad 1.6x1mm, TI Recommended"
  rrect33% 0.45x0.3 smd: 1(-0.975,0.65) 2(-0.975,0) 3(-0.975,-0.65) 4(0.975,-0.65) 5(0.975,0) 6(0.975,0.65)
  rrect14% 1x0.7 on Top Paste: 7(0,-0.45) 7(0,0.45)
  rrect10% 1x1.6 smd paste-0.5: 7(0,0)
  silkscreen extent -1.05,-1.2 1.05,1.2, body extent -1.05,-1.05 1.05,1.05, height 0.81
DVE0016A [mm] "SO-MOD-16"
  rrect17% 1.65x0.6 smd: 1(-4.875,4.445) 2(-4.875,3.175) 3(-4.875,1.905) 4(-4.875,0.635) 5(-4.875,-0.635) 6(-4.875,-1.905) 7(-4.875,-3.175) 8(-4.875,-4.445) 9(4.875,-4.445) 10(4.875,-3.175) 11(4.875,-1.905) 12(4.875,-0.635) 13(4.875,0.635) 14(4.875,1.905) 15(4.875,3.175) 16(4.875,4.445)
  body extent -5.17,-5.15 5.17,5.15, height 2.59
DW0016B_HV [mm] "SOIC-16, HV/isolation option"
  rrect17% 1.65x0.6 smd: 1(-4.875,4.445) 2(-4.875,3.175) 3(-4.875,1.905) 4(-4.875,0.635) 5(-4.875,-0.635) 6(-4.875,-1.905) 7(-4.875,-3.175) 8(-4.875,-4.445) 9(4.875,-4.445) 10(4.875,-3.175) 11(4.875,-1.905) 12(4.875,-0.635) 13(4.875,0.635) 14(4.875,1.905) 15(4.875,3.175) 16(4.875,4.445)
  body extent -5.17,-5.15 5.17,5.15, height 2.59
DWV0008A [mm] "SOIC, 8-Leads, Body 5.95x7.6mm (max), Pitch 1.27mm"
  rrect17% 1.8x0.6 smd: 1(-5.45,1.905) 2(-5.45,0.635) 3(-5.45,-0.635) 4(-5.45,-1.905) 5(5.45,-1.905) 6(5.45,-0.635) 7(5.45,0.635) 8(5.45,1.905)
  silkscreen extent -6.25,-2.95 2.98,2.95, body extent -5.77,-2.92 5.77,2.93, height 2.67
FCC_disclaimer [mil]
Fiducial10-20 [mm]
  round 1 smd mask+0.5: 1(0,0)
  Top Layer keep-out circle w1.178: c0,0 r0.5
FP-BLM31KN121SZ1L_1206-MFG [mm]
  rrect9% 1.15x1.8 smd paste+0 mask+0: 1(-1.575,0) 2(1.575,0)
  silkscreen extent -0.63,-0.9 0.63,0.9, body extent -2.25,-1 2.25,1, height 0.25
